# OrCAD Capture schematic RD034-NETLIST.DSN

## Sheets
1 6: size A3
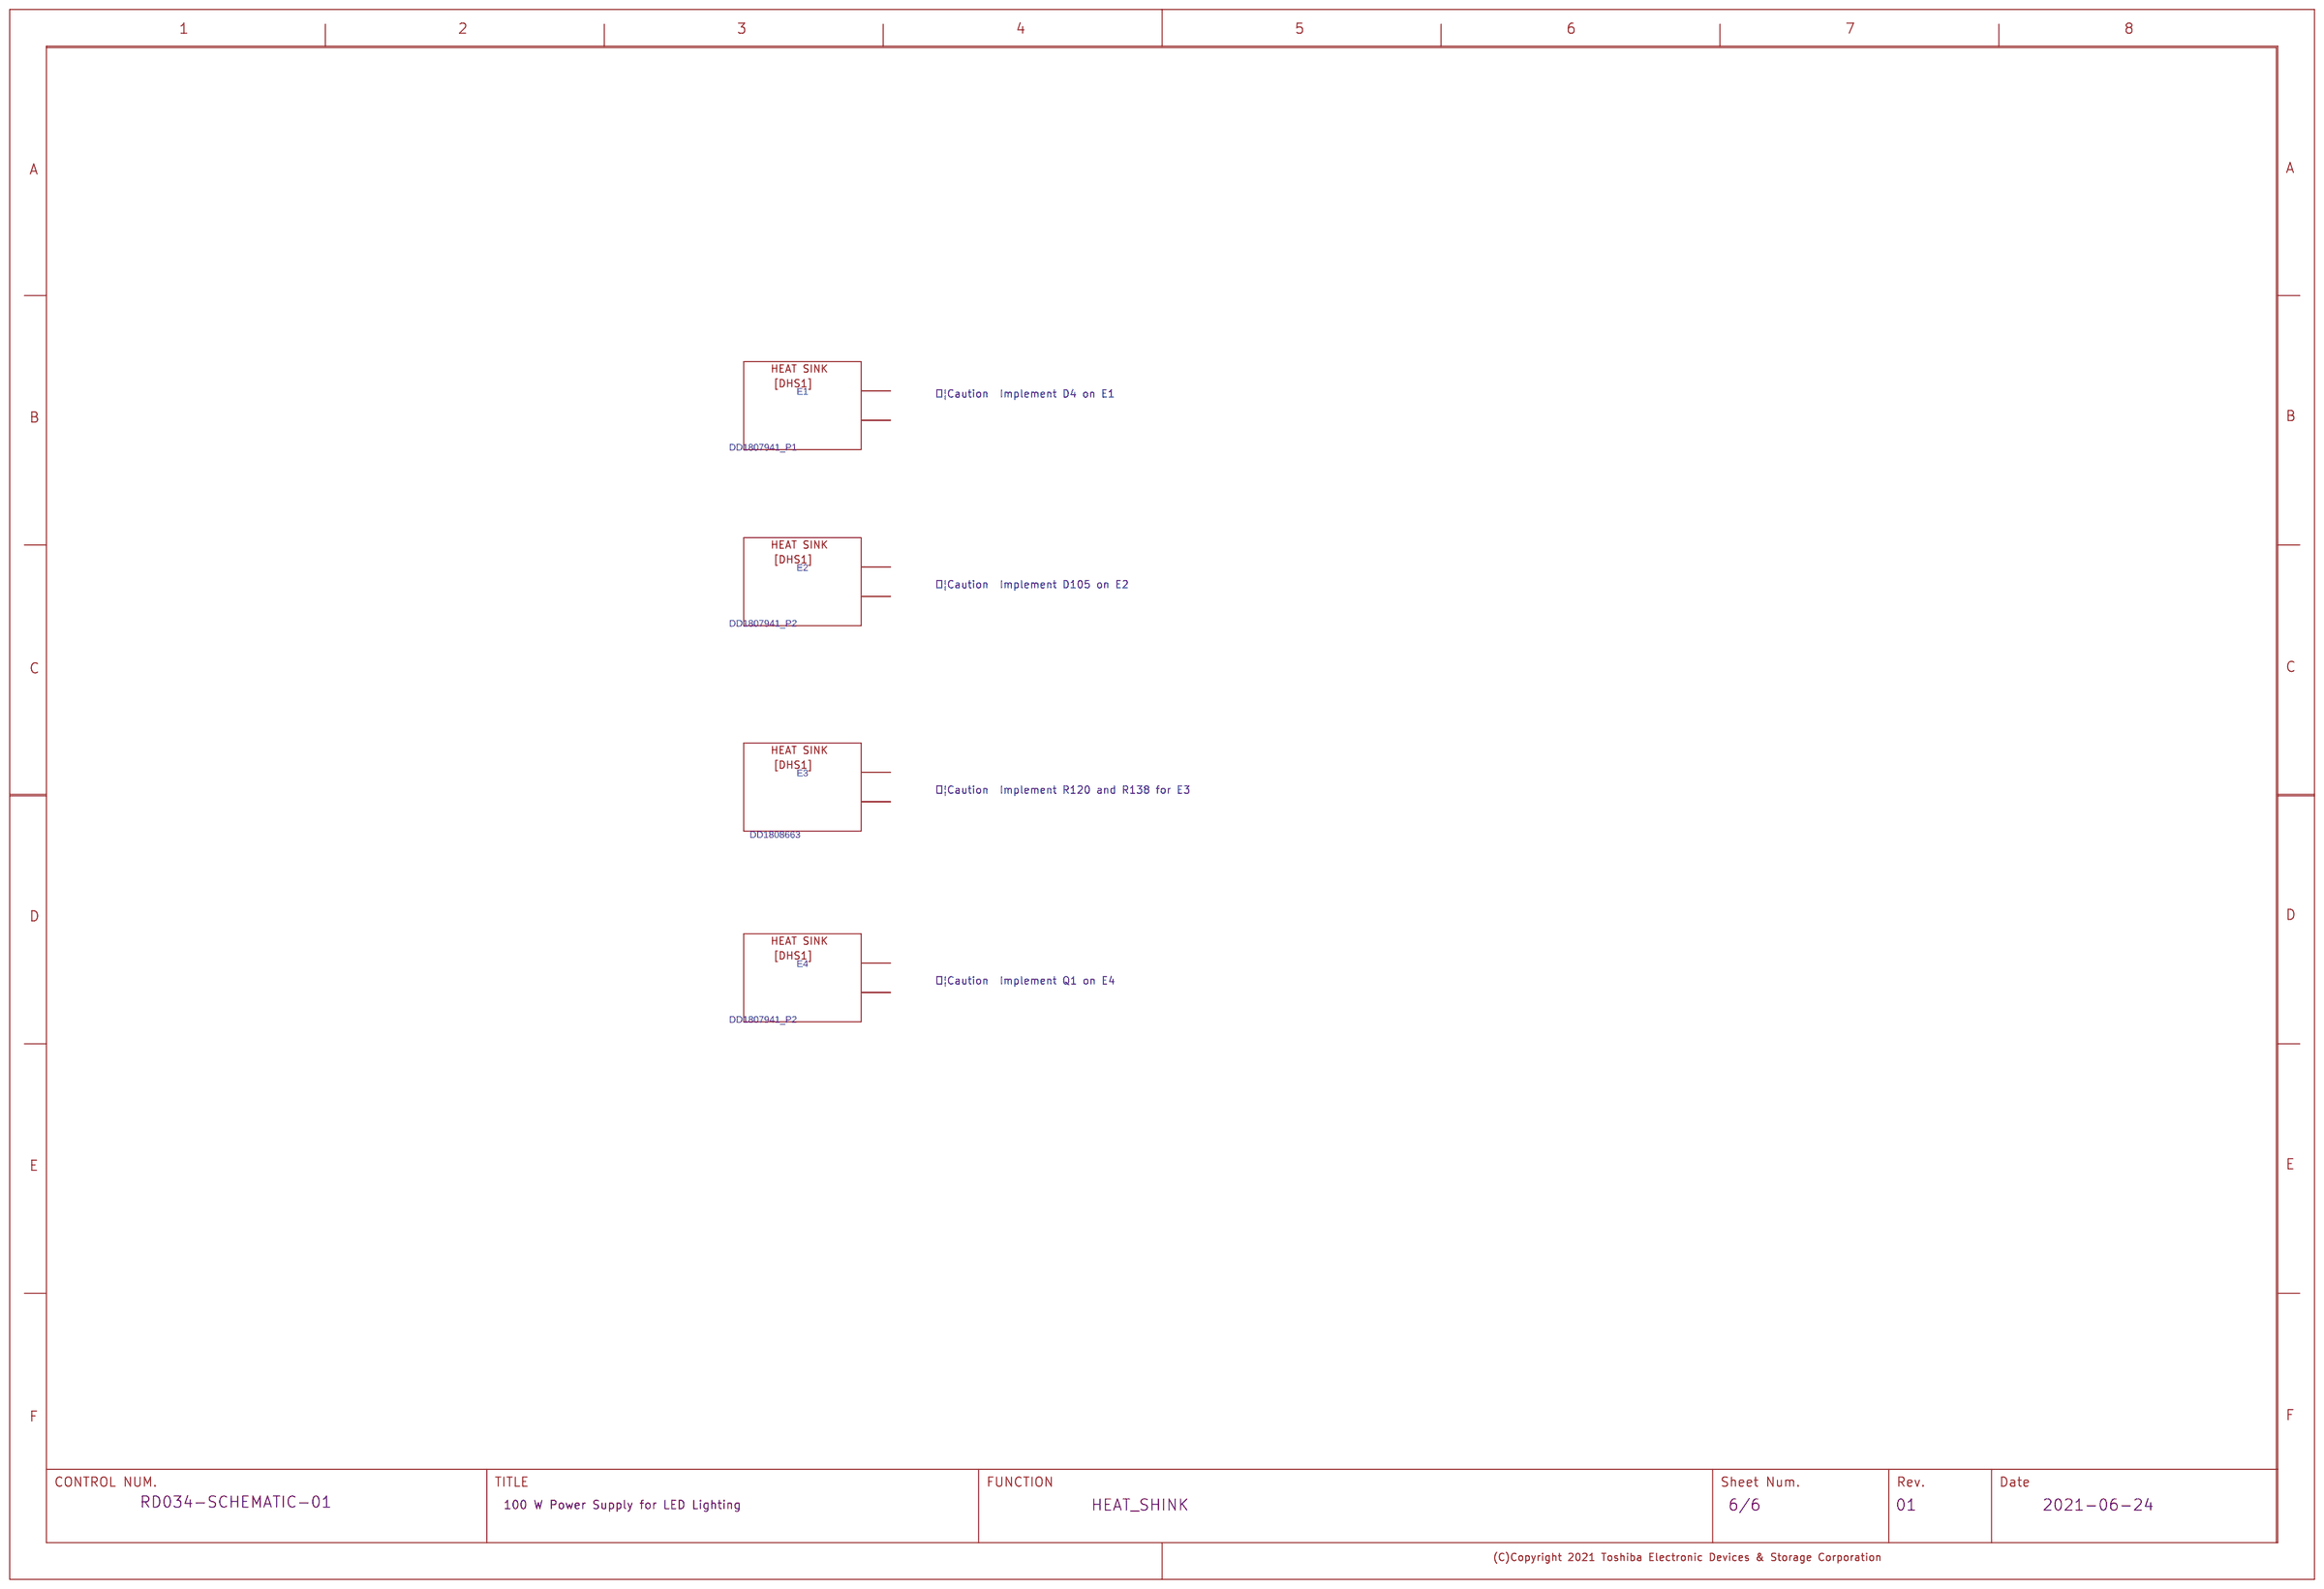
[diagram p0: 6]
2 5: size A3
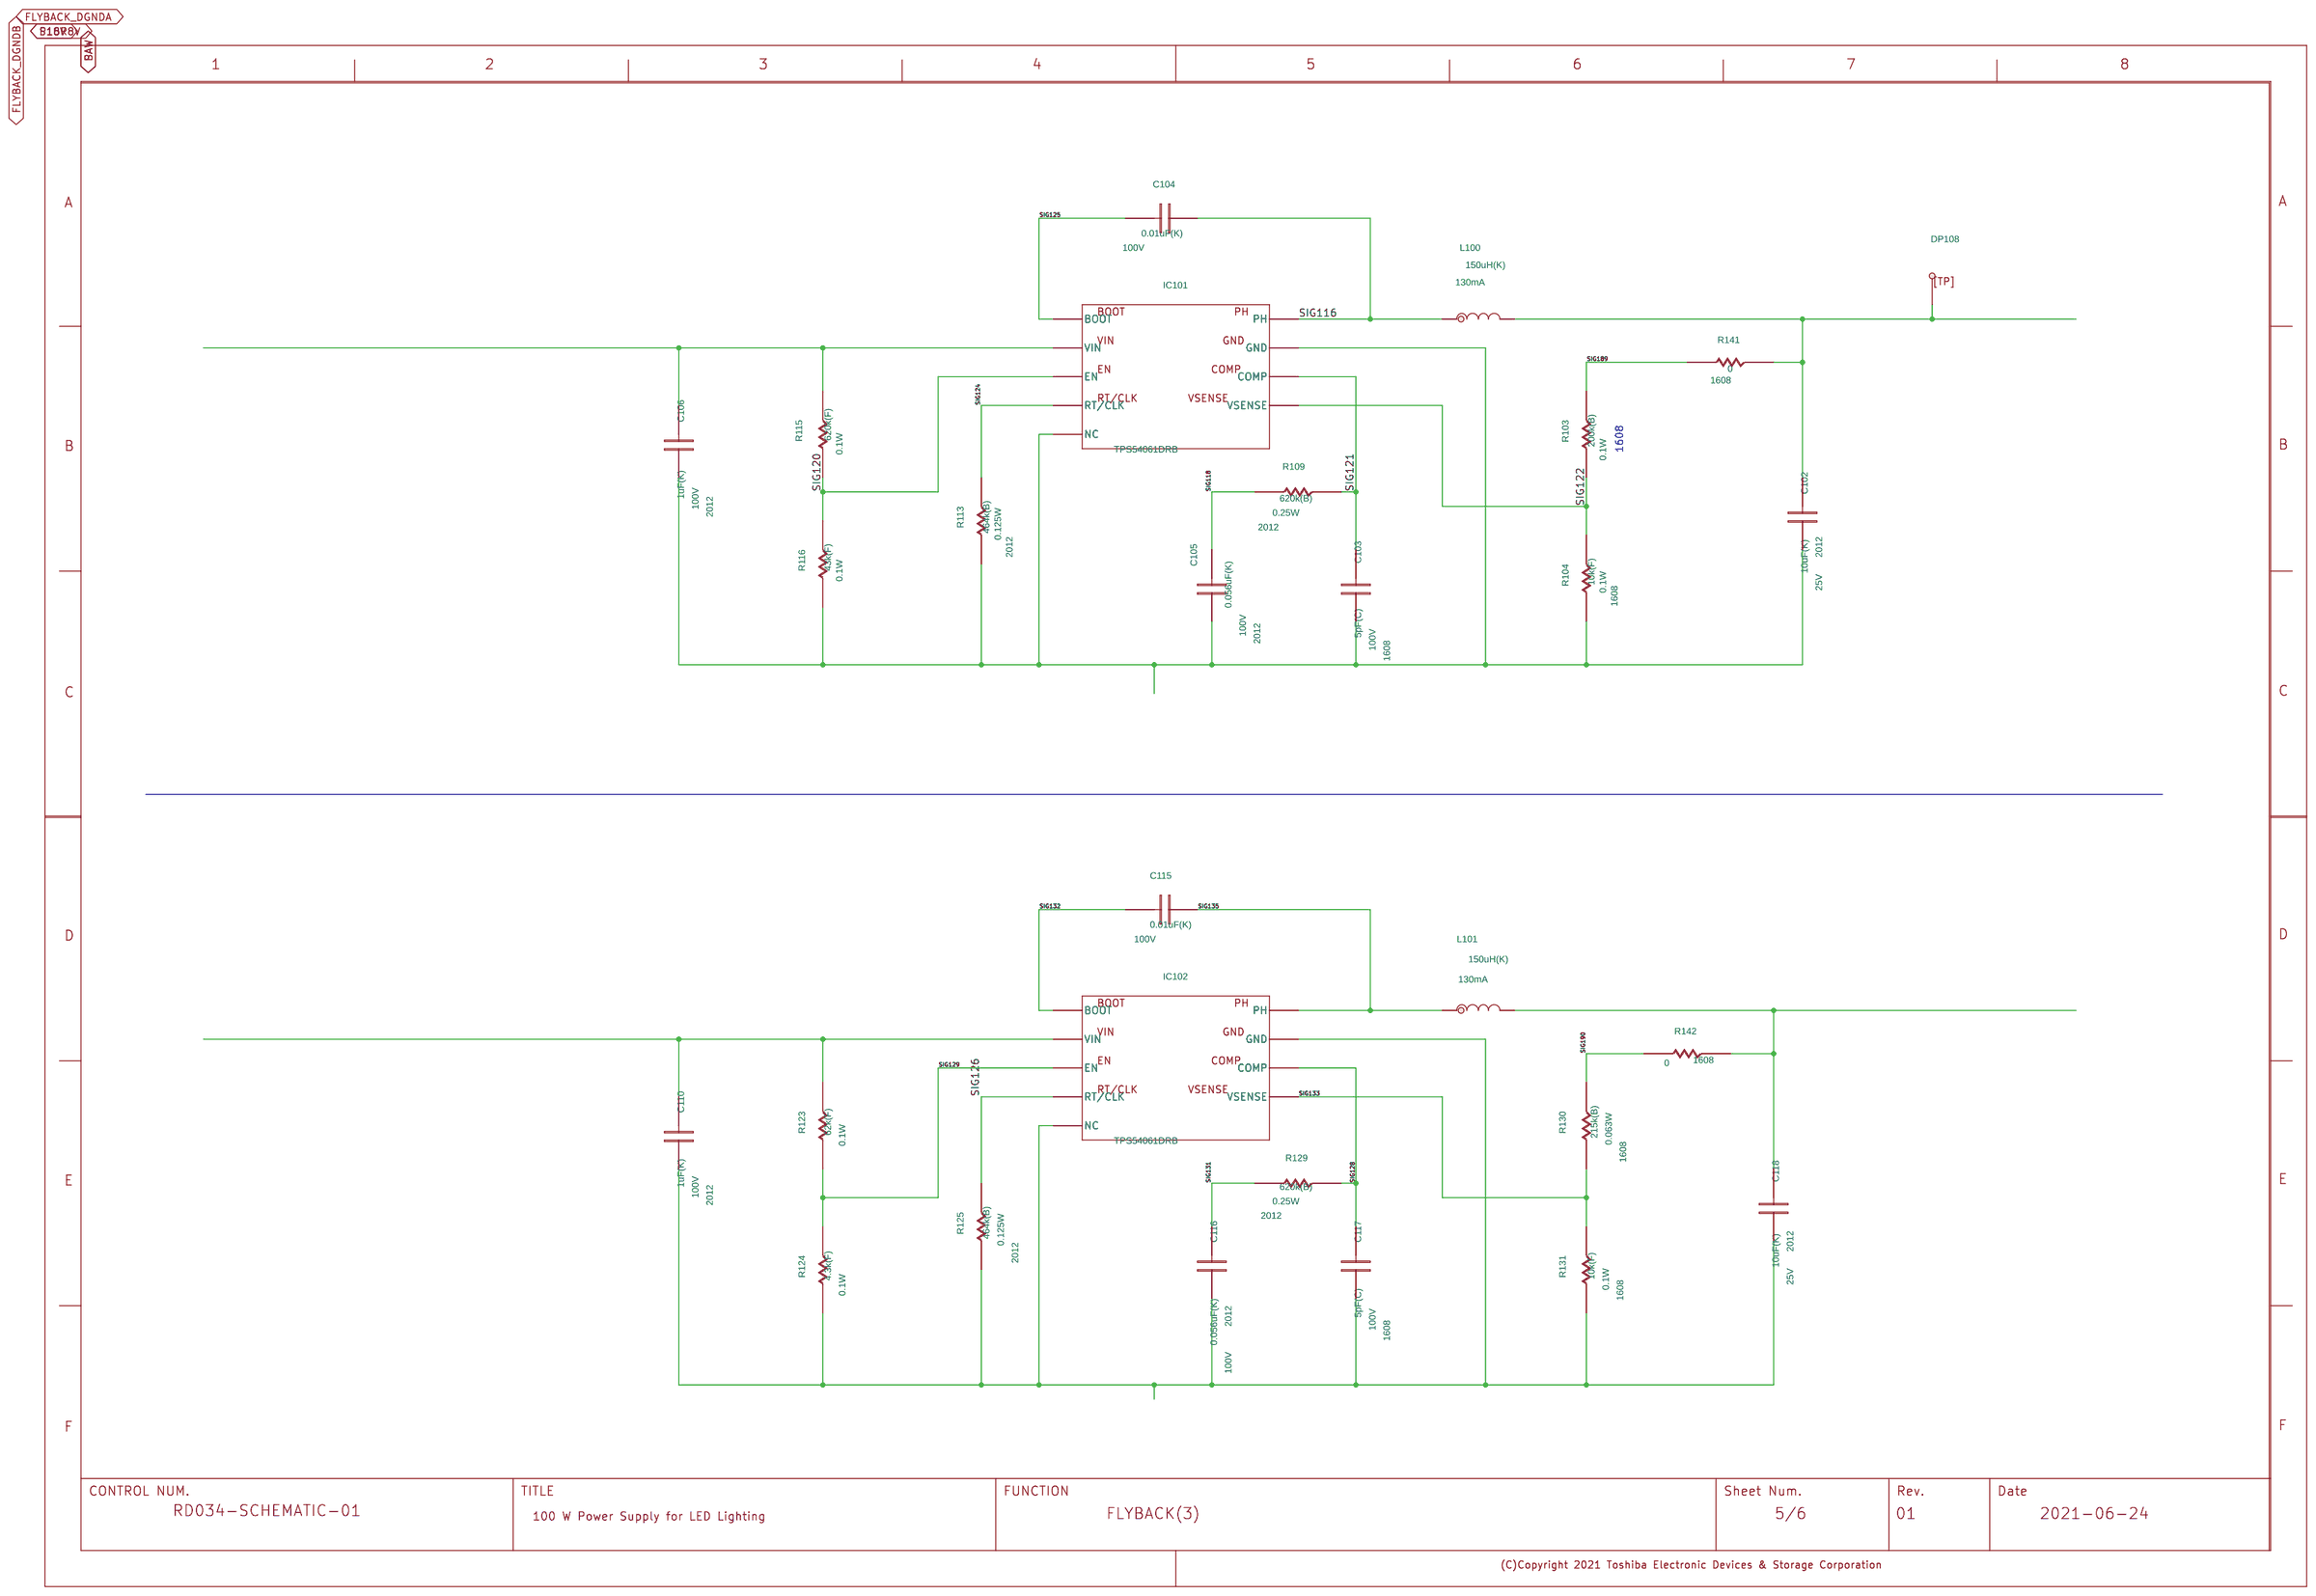
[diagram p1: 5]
3 4: size A3
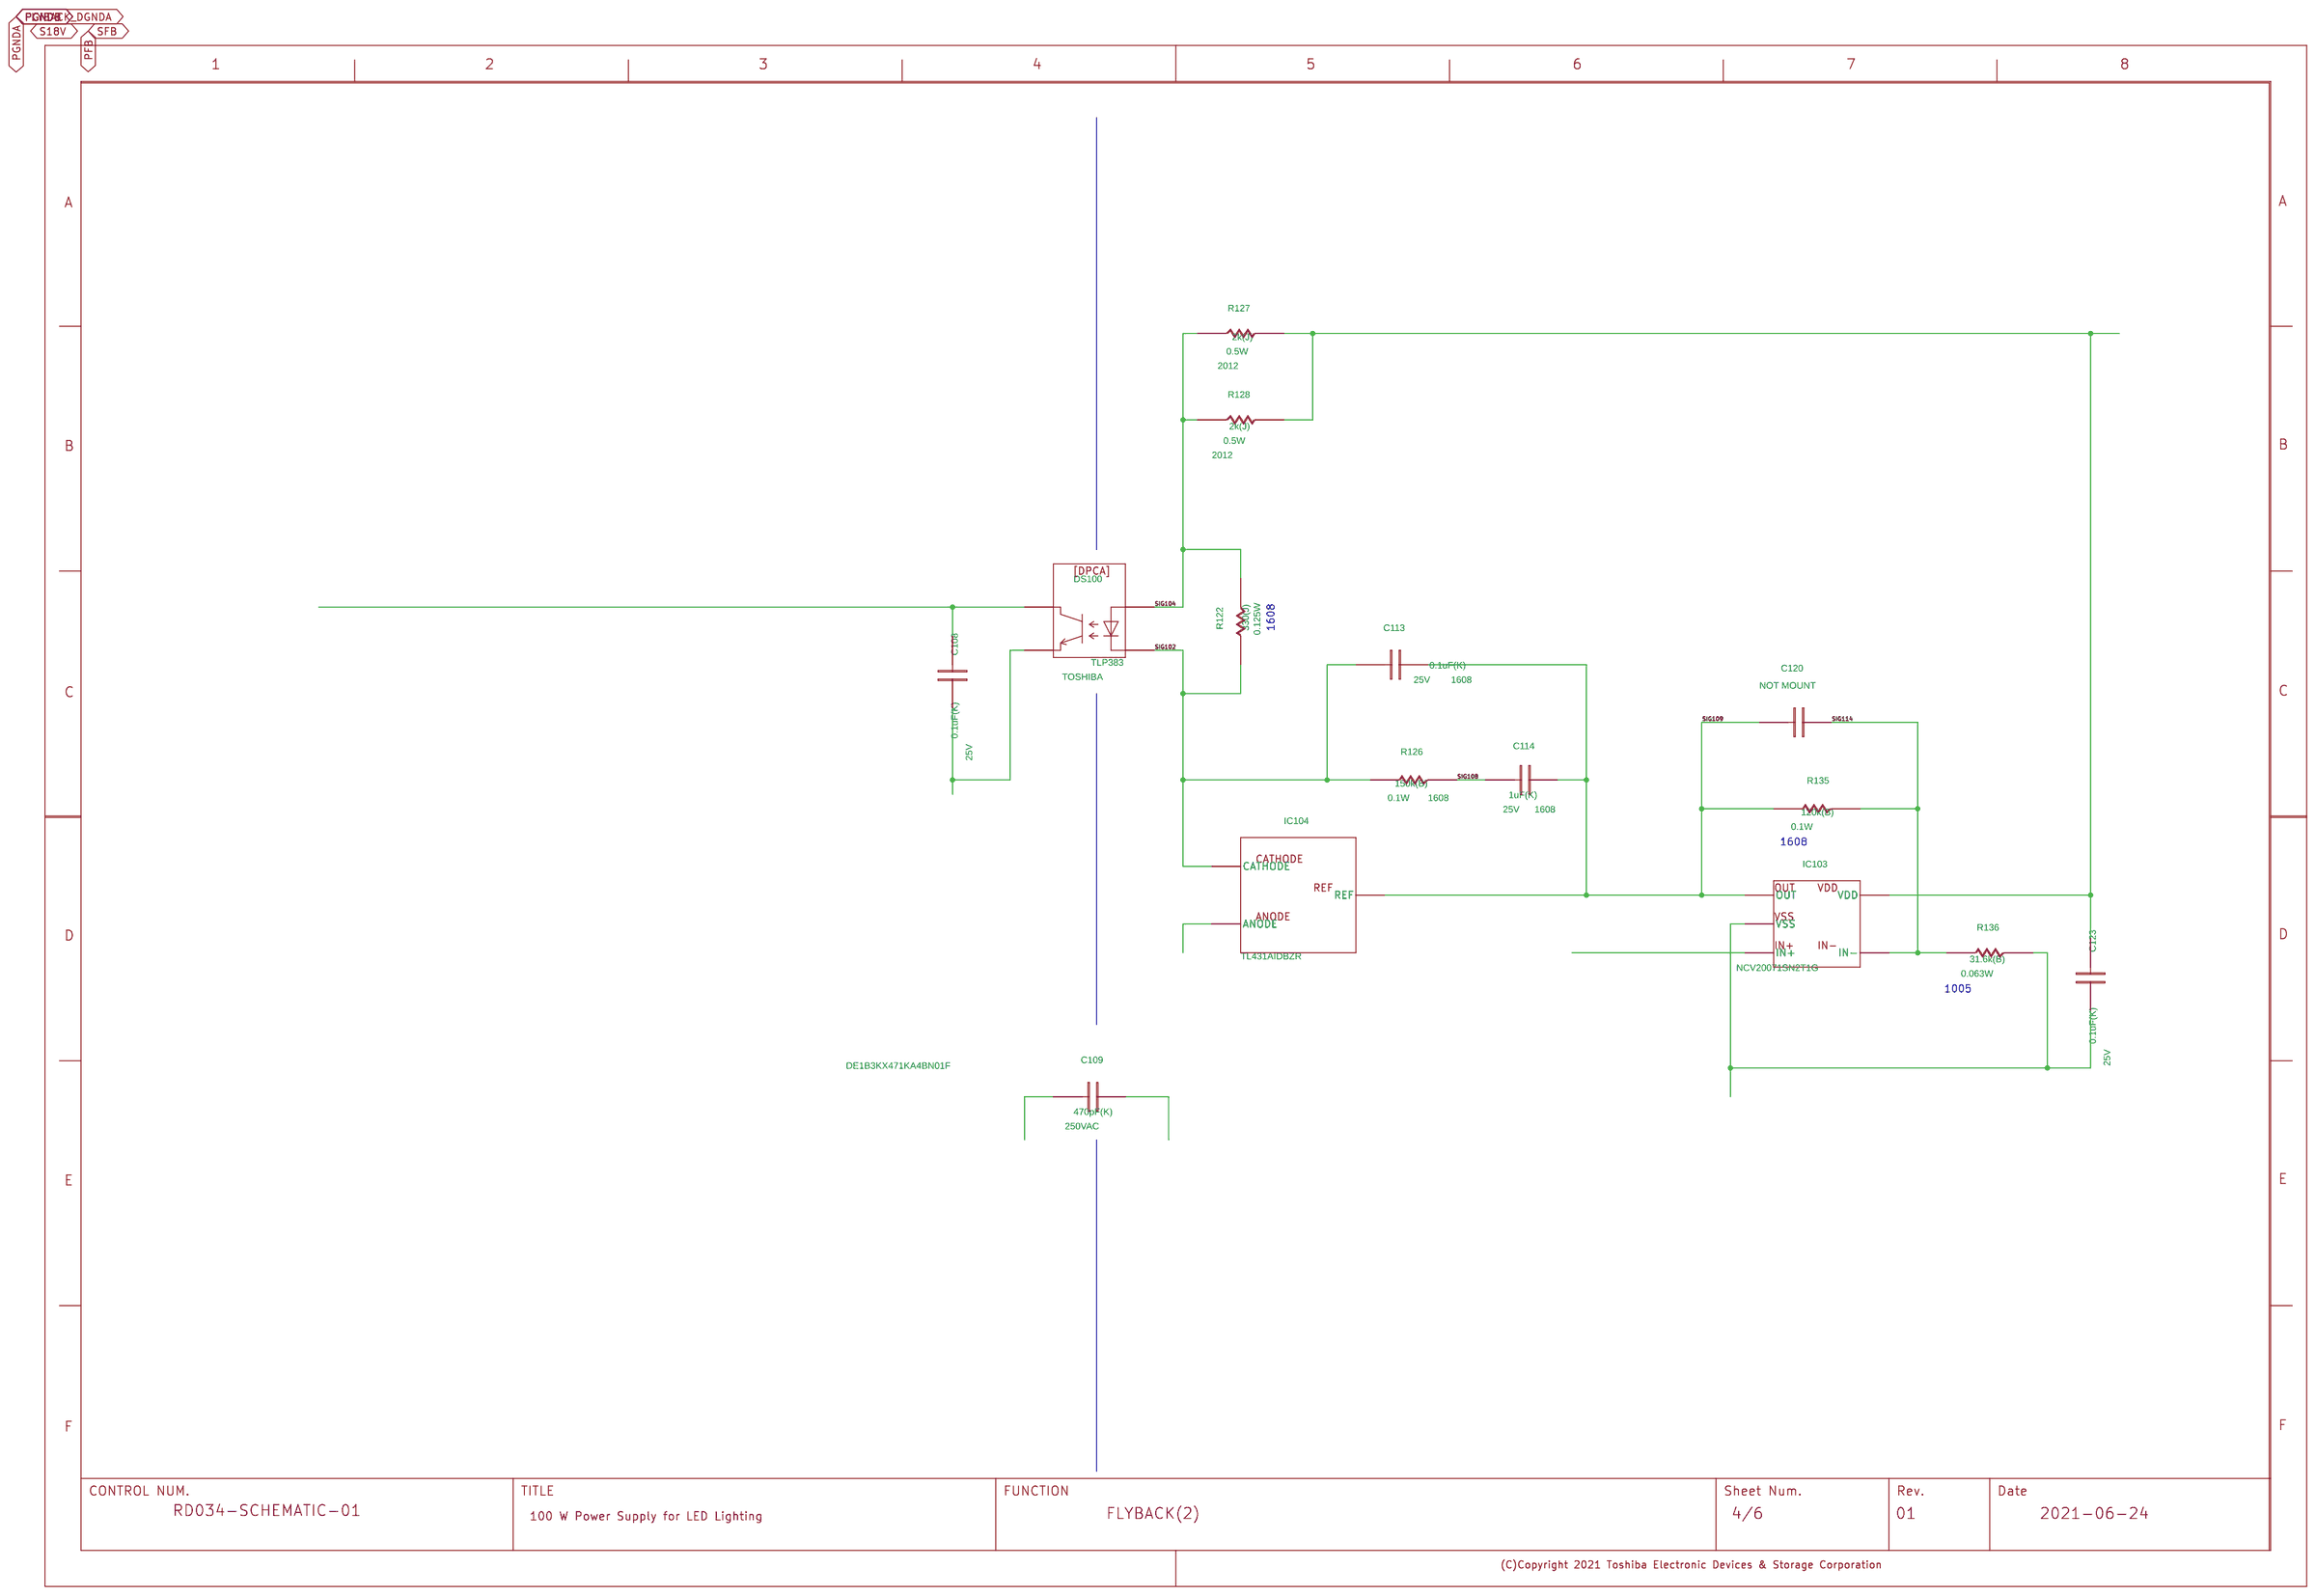
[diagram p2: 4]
4 3: size A3
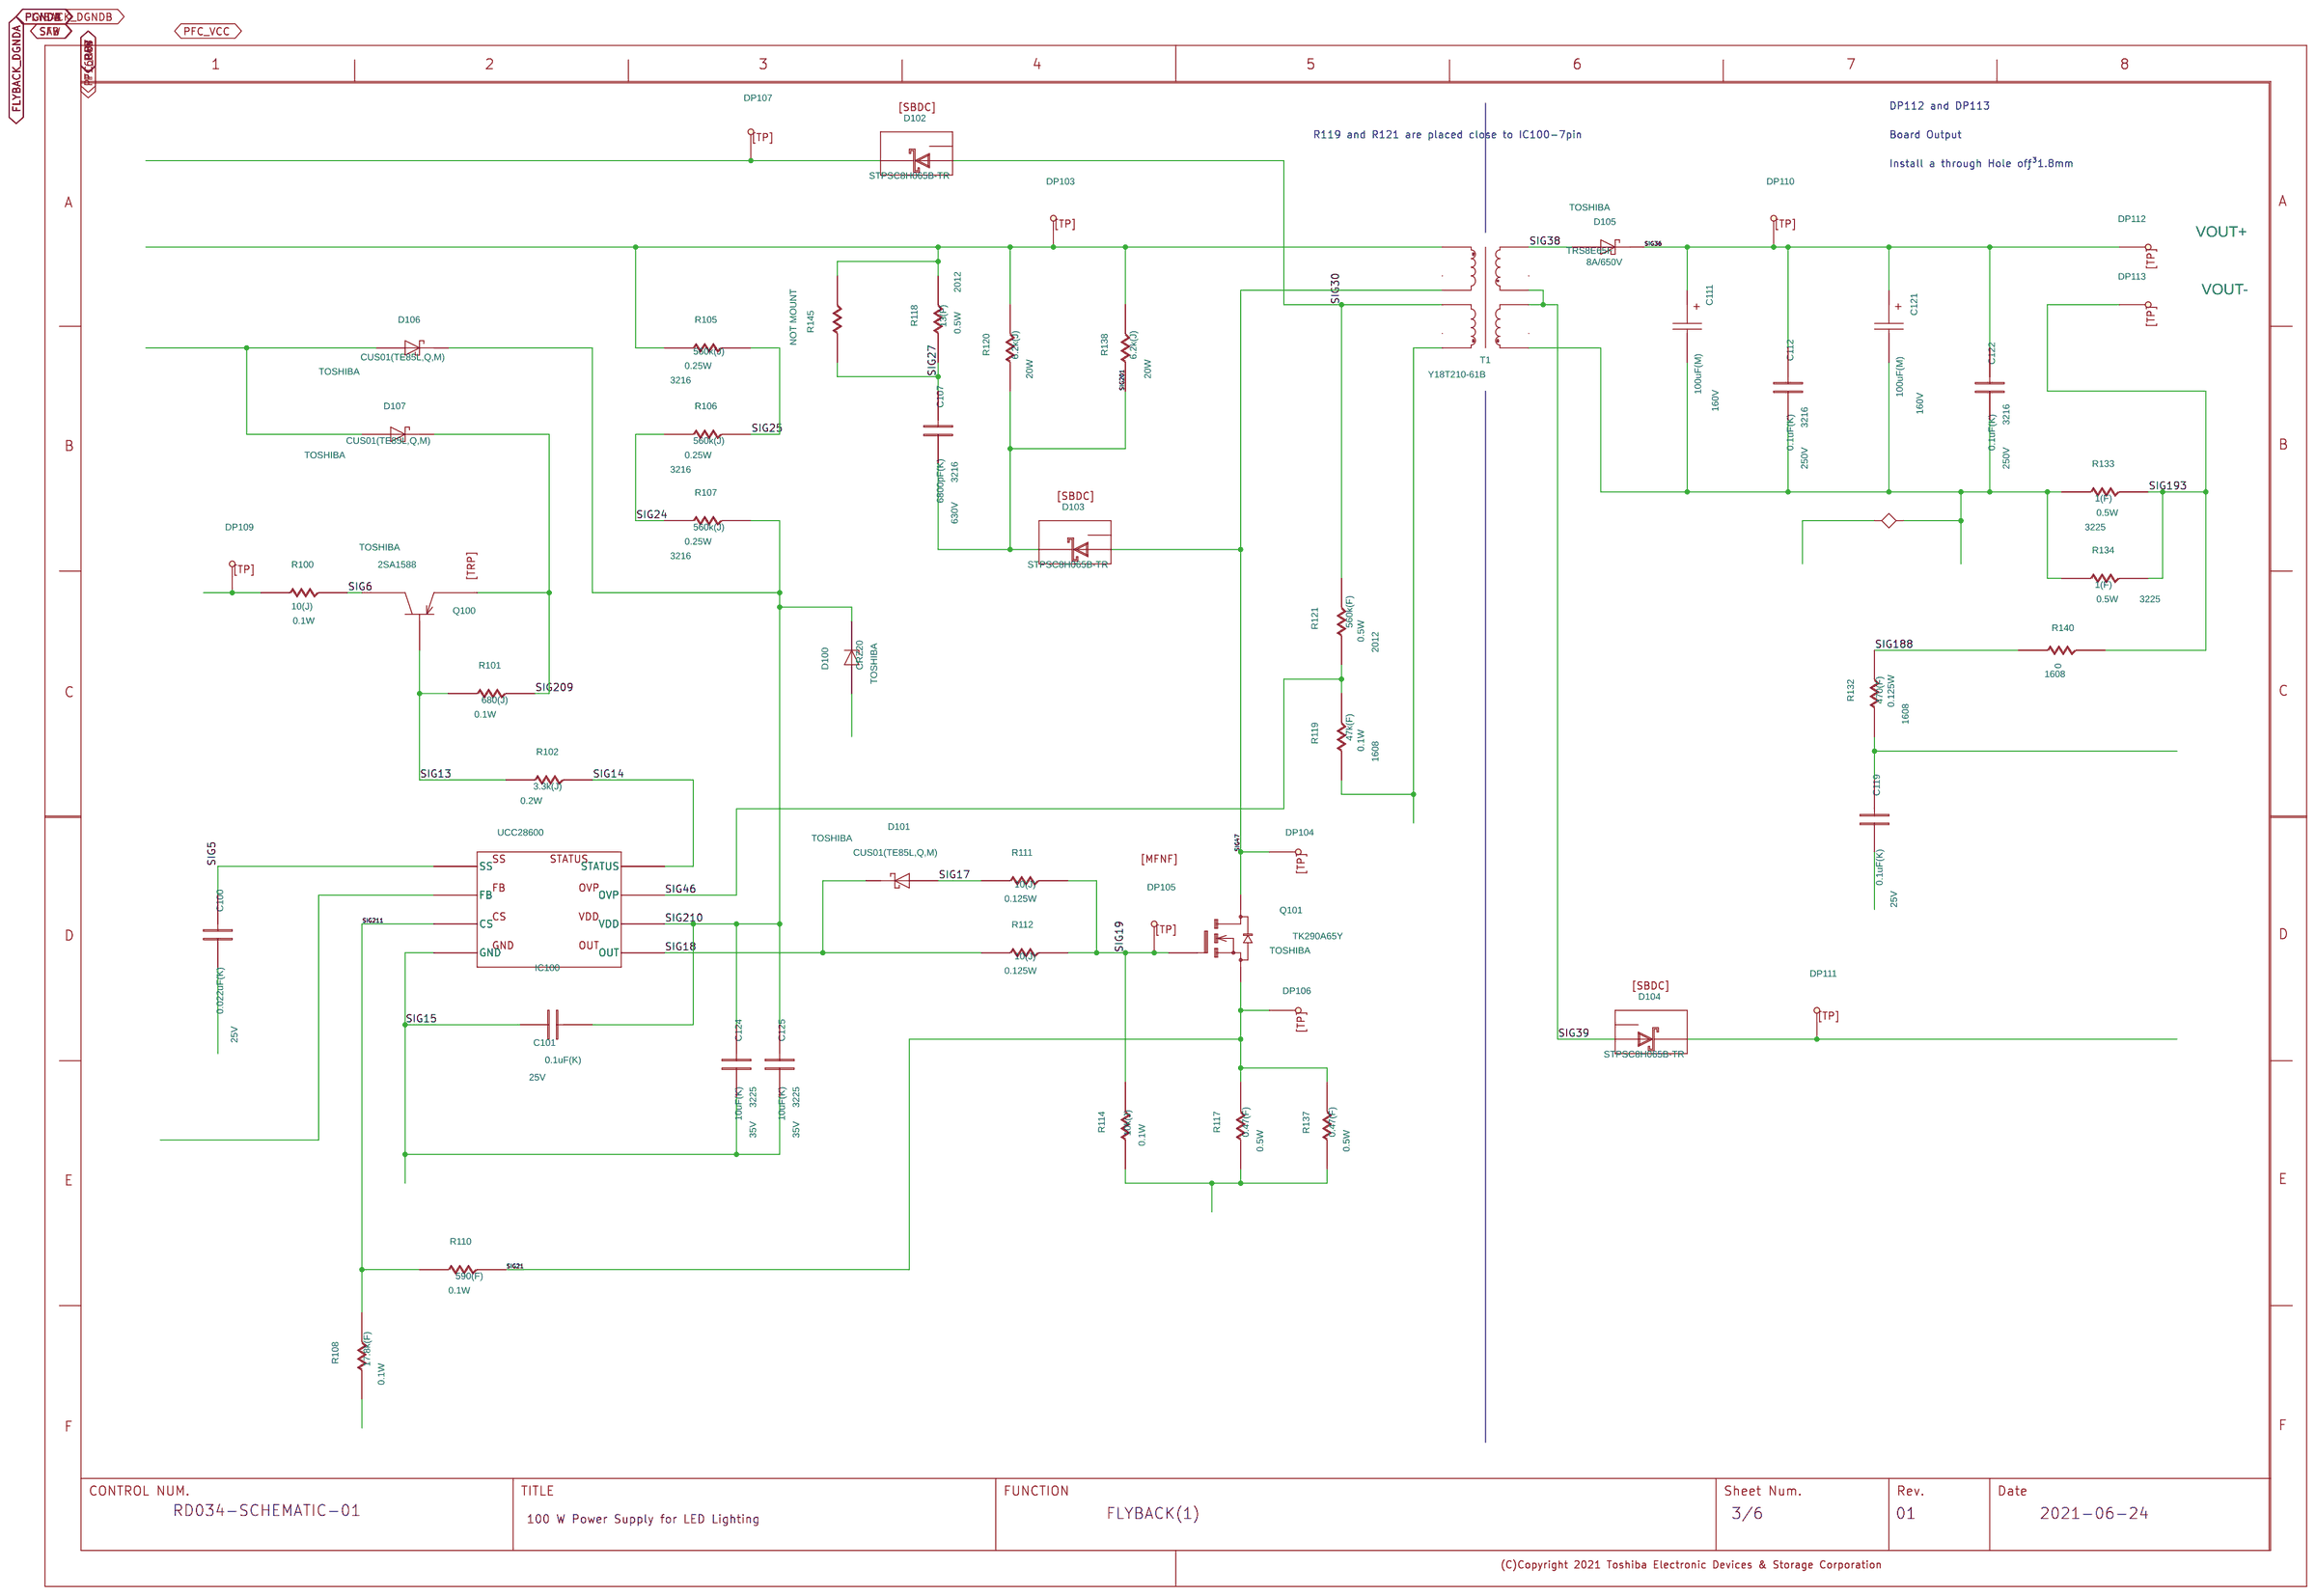
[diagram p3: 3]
5 2: size A3
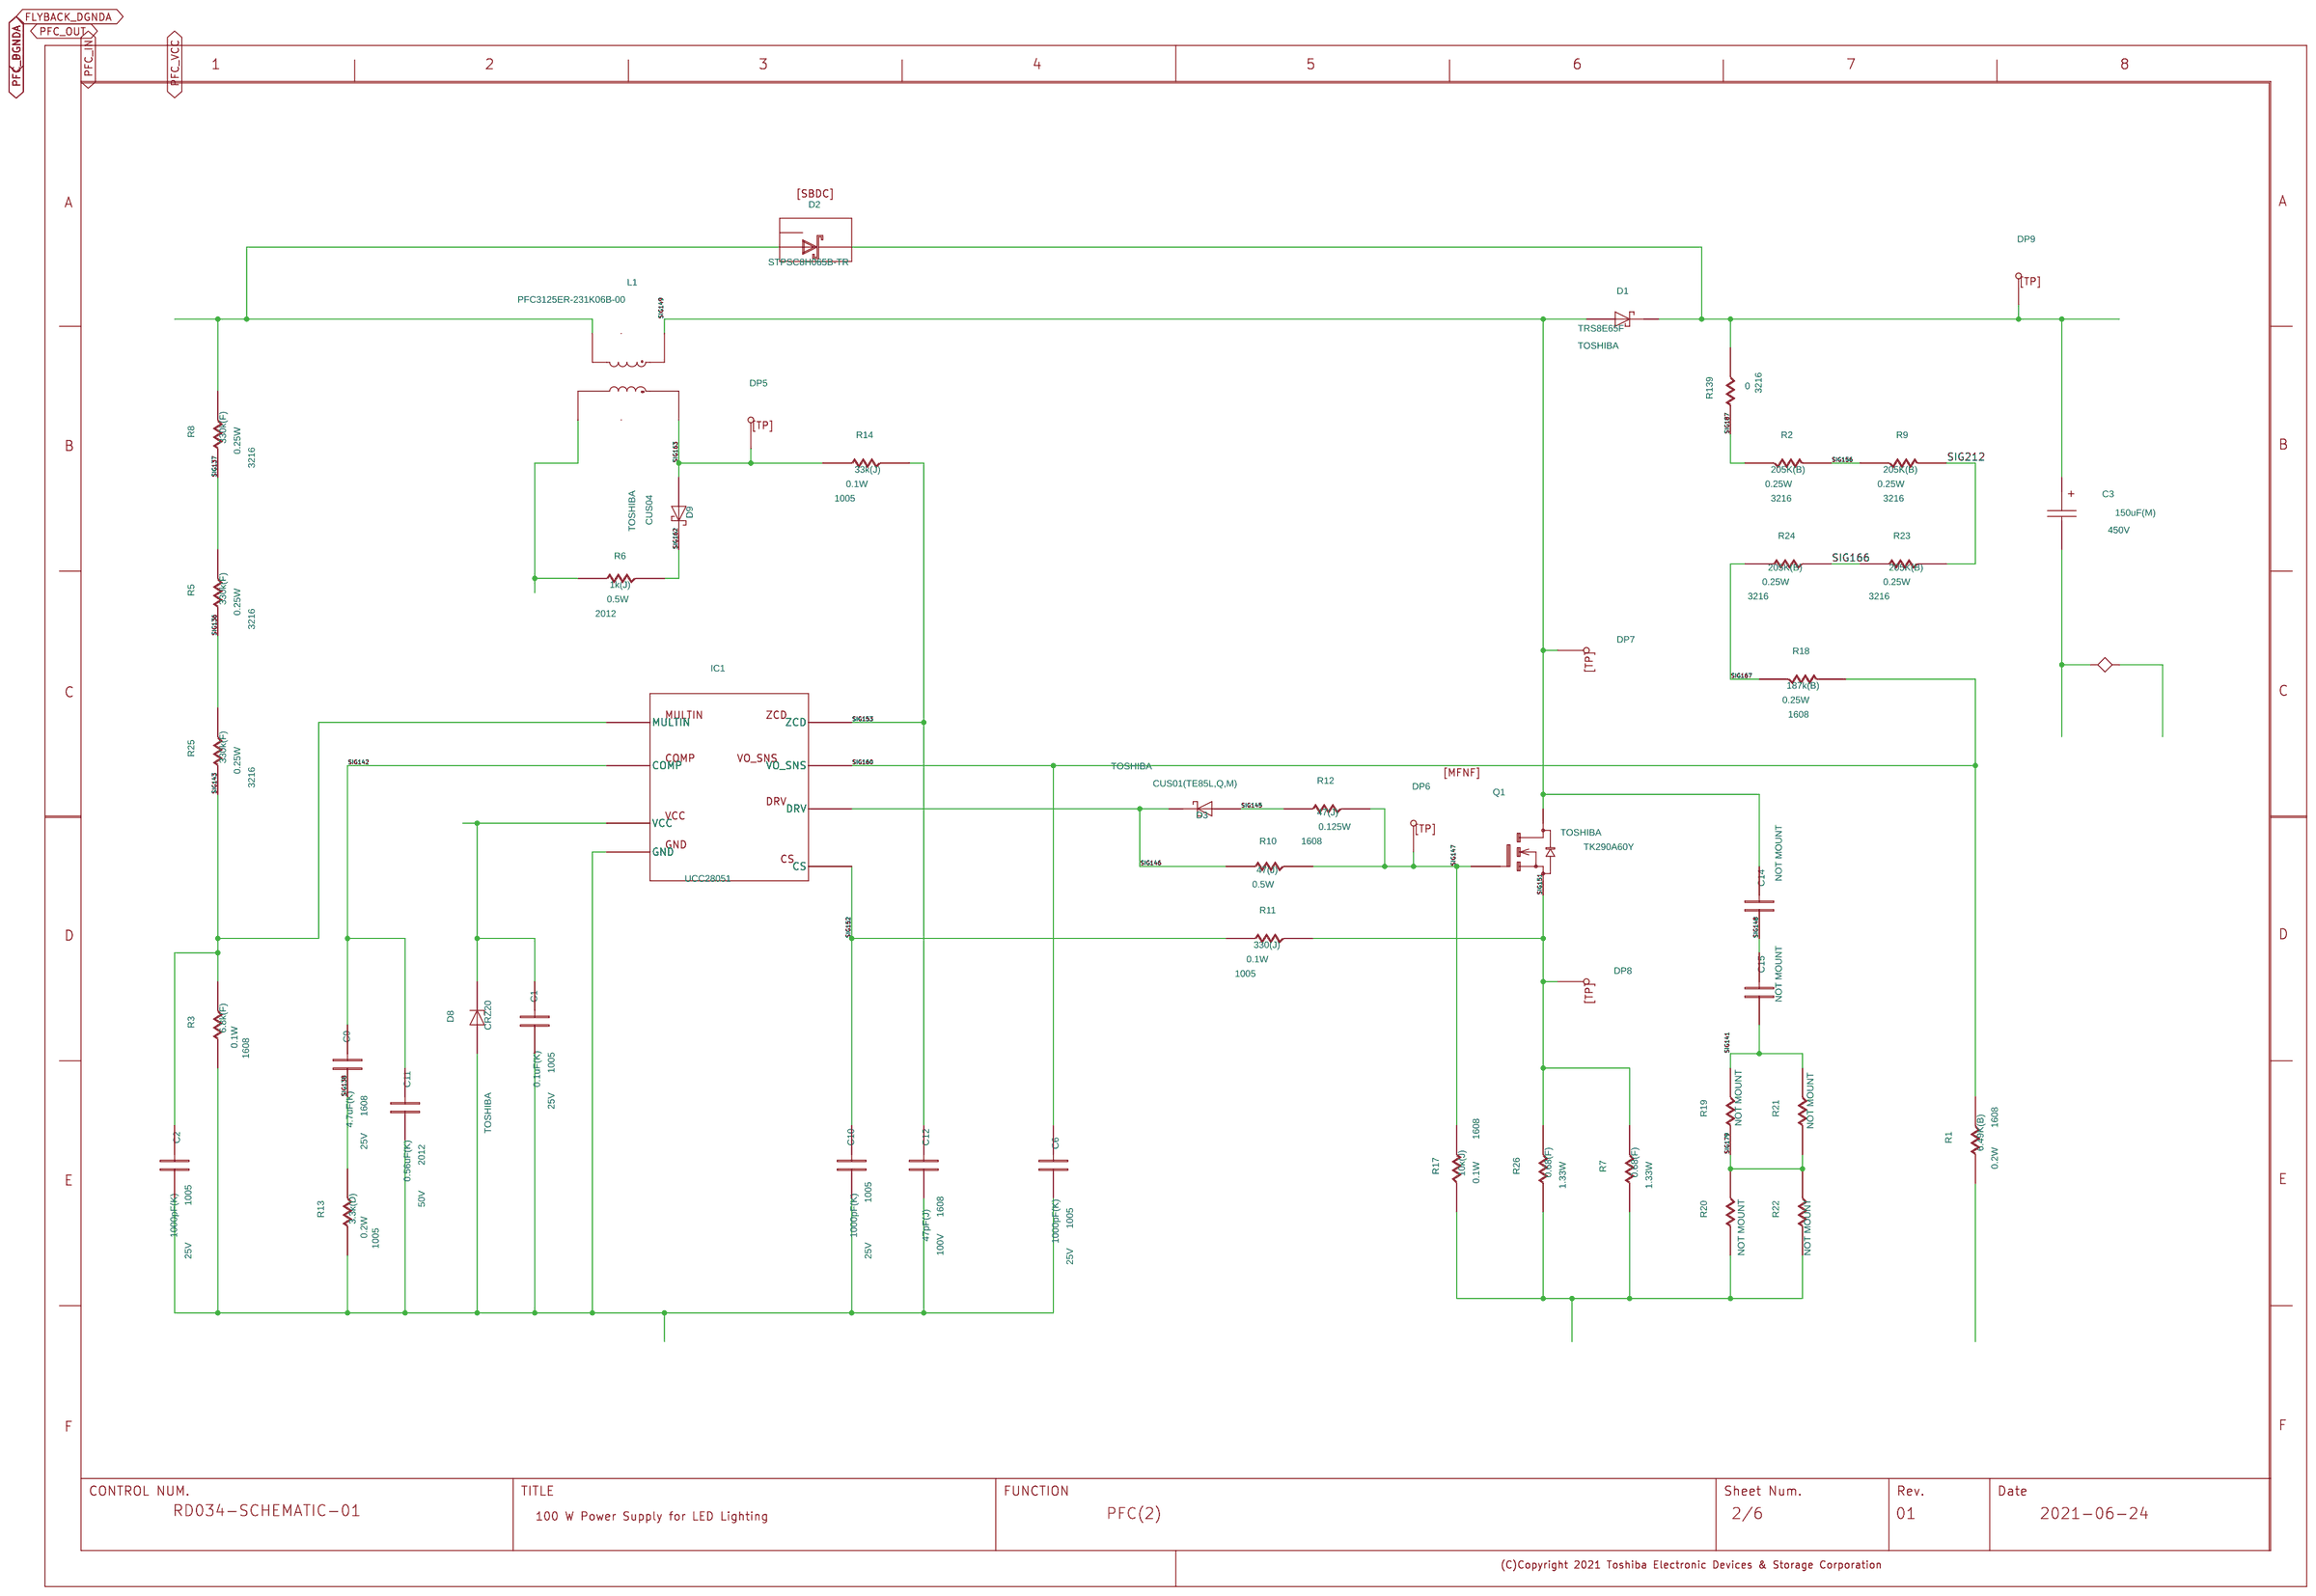
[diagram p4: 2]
6 1: size A3
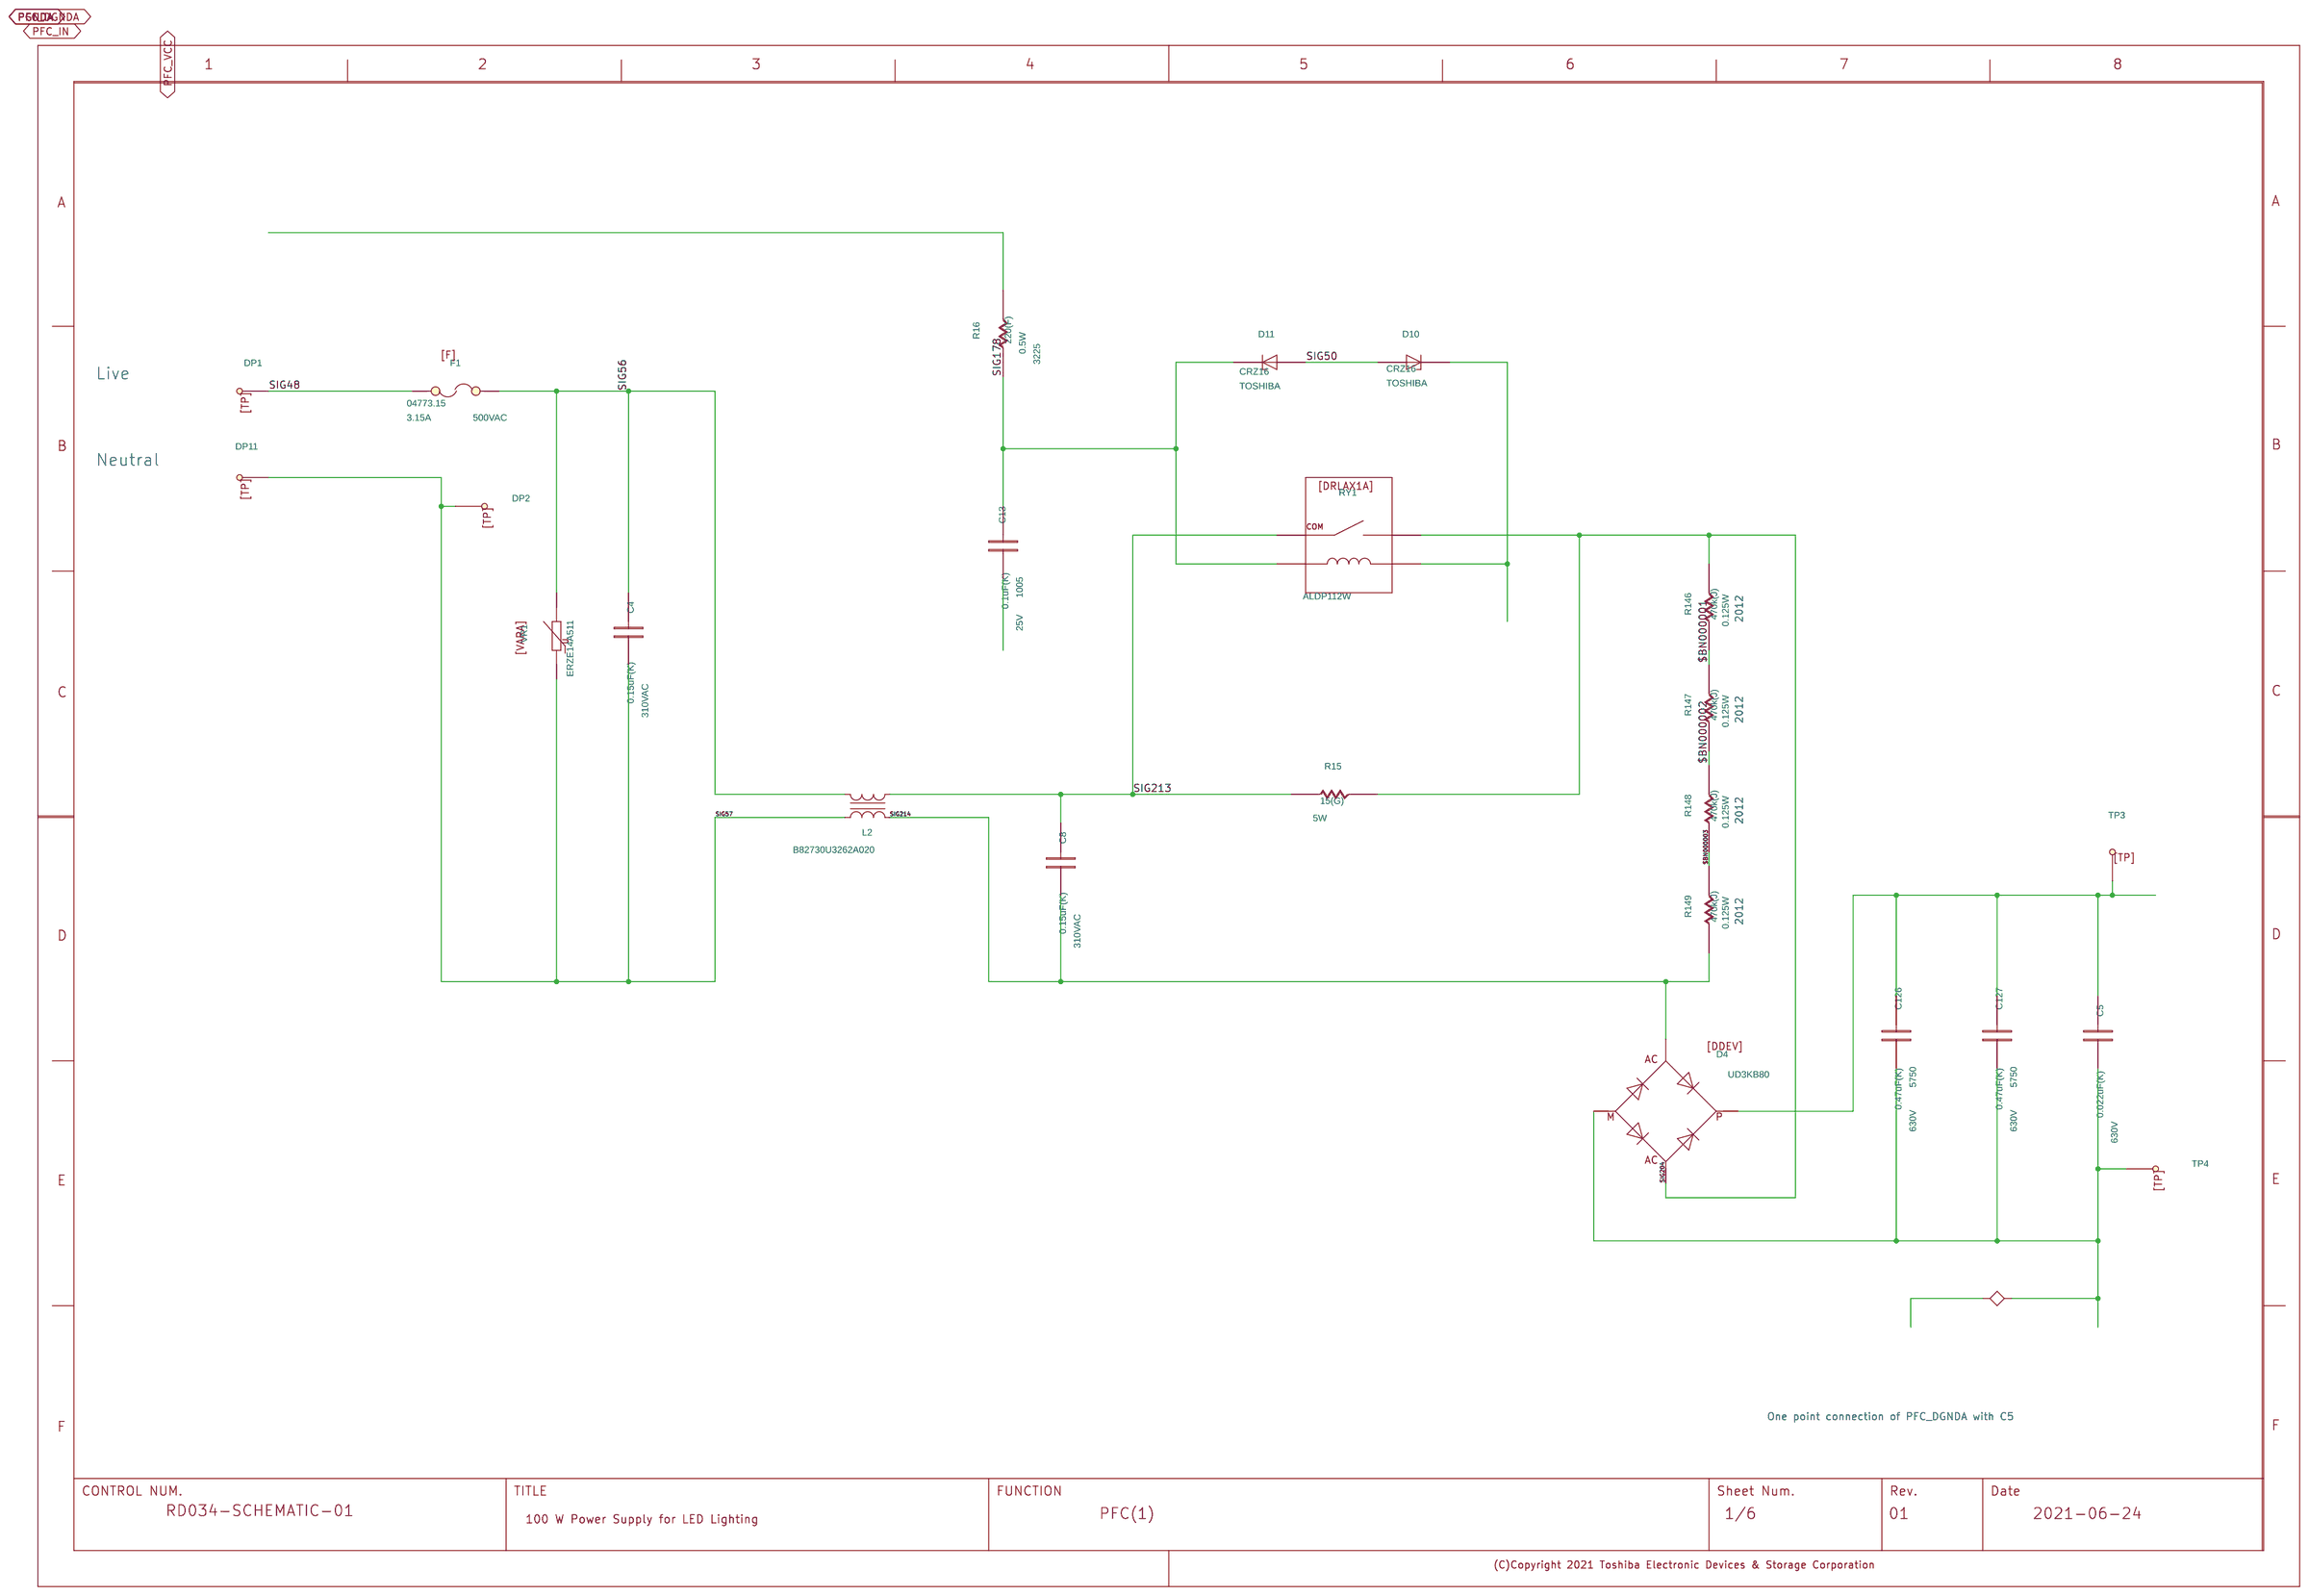
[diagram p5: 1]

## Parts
sheet 1
C4  DC
C5  DC
C8  DC
C13  DC
C126  DC
C127  DC
D4  DDEV
D10  DZD2
D11  DZD2
DP1  DTP
DP2  DTP
DP11  DTP
F1  DF
L2  CMF_2P_CMF_2P
R15  DR
R16  DR
R146  DR
R147  DR
R148  DR
R149  DR
RY1  DRLAX1A
STAR2  STAR2
TP3  DTP
TP4  DTP
U?#5  WAKU_DEF100_2021
VR1  DVARA
sheet 2
C1  DC
C2  DC
C3  DCP2
C6  DC
C9  DC
C10  DC
C11  DC
C12  DC
C14  DC
C15  DC
D1  DSBD2
D2  DSBDC2
D3  DSBD2
D8  DZD2
D9  DSBD2
DP5  DTP
DP6  DTP
DP7  DTP
DP8  DTP
DP9  DTP
IC1  UCC28051
L1  PFC3125ER-231K06B-00
Q1  DMFNF
R1  DR
R2  DR
R3  DR
R5  DR
R6  DR
R7  DR
R8  DR
R9  DR
R10  DR
R11  DR
R12  DR
R13  DR
R14  DR
R17  DR
R18  DR
R19  DR
R20  DR
R21  DR
R22  DR
R23  DR
R24  DR
R25  DR
R26  DR
R139  DR
STAR1  STAR2
U?#4  WAKU_DEF100_2021
sheet 3
C100  DC
C101  DC
C107  DC
C111  DCP2
C112  DC
C119  DC
C121  DCP2
C122  DC
C124  DC
C125  DC
D100  DZD2
D101  DSBD2
D102  DSBDC2
D103  DSBDC2
D104  DSBDC2
D105  DSBD2
D106  DSBD2
D107  DSBD2
DP103  DTP
DP104  DTP
DP105  DTP
DP106  DTP
DP107  DTP
DP109  DTP
DP110  DTP
DP111  DTP
DP112  DTP
DP113  DTP
IC100  UCC28600
Q100  DTRP
Q101  DMFNF
R100  DR
R101  DR
R102  DR
R105  DR
R106  DR
R107  DR
R108  DR
R110  DR
R111  DR
R112  DR
R114  DR
R117  DR
R118  DR
R119  DR
R120  DR
R121  DR
R132  DR
R133  DR
R134  DR
R137  DR
R138  DR
R140  DR
R145  DR
STAR3  STAR2
T1  TRANS1
U?#3  WAKU_DEF100_2021
sheet 4
C108  DC
C109  DC
C113  DC
C114  DC
C120  DC
C123  DC
DS100  TLP383
IC103  NCV20071SN2T1G
IC104  TL431AIDBZR
R122  DR
R126  DR
R127  DR
R128  DR
R135  DR
R136  DR
U?#2  WAKU_DEF100_2021
sheet 5
C102  DC
C103  DC
C104  DC
C105  DC
C106  DC
C110  DC
C115  DC
C116  DC
C117  DC
C118  DC
DP108  DTP
IC101  TPS54061DRB2
IC102  TPS54061DRB2
L100  DL1D
L101  DL1D
R103  DR
R104  DR
R109  DR
R113  DR
R115  DR
R116  DR
R123  DR
R124  DR
R125  DR
R129  DR
R130  DR
R131  DR
R141  DR
R142  DR
U?#1  WAKU_DEF100_2021
sheet 6
E1  DHS1
E2  DHS1
E3  DHS1
E4  DHS1
U?#6  WAKU_DEF100_2021

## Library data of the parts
C4 C8 = DC: ADSCNVFLAG: ON; CAPACITANCETOLE: M; CDMASTERCADCELG: RD1001; COMPCOMMENT: 0.15Ê/10%/310u`b ;Wurth Electronics ;890334023025 ;- ;13~7~12o; COMPONENTTYPE: 4; FNLEADFREETHET1GT2GMCTH1: N_N_N; GCOUNT: 1; ICX_PART_MODEL: CON_330n; MAXGCOUNT: 1; NOMINALCAPACITA: 330n; OUMECLASSIFICATION: ƒtƒBƒ‹ƒƒRƒ“ƒfƒ“ƒT; OUMEMAKERKATAMEI: B32922C3334M; OUMEPARTTYPE: C; PARTNAME: 890334023025; RATEDVOLTAGE: 305; VAL1: 0.15uF(K); VAL2: 310VAC; VAL3: 890334023025
C5 = DC: ADSCNVFLAG: ON; CAPACITANCETOLE: M; CDMASTERCADCELG: RD1001; COMPCOMMENT: 0.022Ê/10%/630V ;Panasonic ;ECQE6223KF ;- ;12.00mm x 5.30mm~11.50; COMPONENTTYPE: 4; FNLEADFREETHET1GT2GMCTH1: N_N_N; GCOUNT: 1; ICX_PART_MODEL: CON_330n; MAXGCOUNT: 1; NOMINALCAPACITA: 330n; OUMECLASSIFICATION: ƒtƒBƒ‹ƒƒRƒ“ƒfƒ“ƒT; OUMEMAKERKATAMEI: B32922C3334M; OUMEPARTTYPE: C; PARTNAME: ECQE6223KF; RATEDVOLTAGE: 305; VAL1: 0.022uF(K); VAL2: 630V; VAL3: ECQE6223KF
C1 C13 C101 C108 C119 C123 = DC: ADSCNVFLAG: ON; ADSCOMPONENTNAME: C_1005; ADSMODELNAME: s_GRM155R61E104KA87D; CAPACITANCETOLE: K; CDMASTERCADCELG: KC0005; COMPCOMMENT: 0.1u/10%/25V ;MURATA ;GRM155R61E104KA87D ;1005 ;-; COMPONENTTYPE: 4; FNLEADFREETHET1GT2GMCTH1: N_N_N; GCOUNT: 1; ICX_PART_MODEL: CON_100n; MAXGCOUNT: 1; NOMINALCAPACITA: 100n; OUMECLASSIFICATION: ƒZƒ‰ƒ~ƒbƒNƒRƒ“ƒfƒ“ƒT; OUMEMAKER: MRT ºc»ì; OUMEMAKERKATAMEI: GRM155R61E104KA87D; OUMEPARTTYPE: C; PARTNAME: GRM155R61E104KA87D; RATEDVOLTAGE: 25; SIZECODESMD: 1005; VAL1: 0.1uF(K); VAL2: 25V; VAL3: GRM155R61E104KA87D
C126 C127 = DC: ADSCNVFLAG: ON; CAPACITANCETOLE: M; CDMASTERCADCELG: RD1001; COMPCOMMENT: 5750; COMPONENTTYPE: 4; FNLEADFREETHET1GT2GMCTH1: N_N_N; GCOUNT: 1; ICX_PART_MODEL: CON_330n; MAXGCOUNT: 1; NOMINALCAPACITA: 330n; OUMECLASSIFICATION: ƒtƒBƒ‹ƒƒRƒ“ƒfƒ“ƒT; OUMEMAKERKATAMEI: B32922C3334M; OUMEPARTTYPE: C; PARTNAME: C5750X7T2J474K250KC; RATEDVOLTAGE: 305; VAL1: 0.47uF(K); VAL2: 630V; VAL3: C5750X7T2J474K250KC
D4 = DDEV: ADSCNVFLAG: ON; ADSCOMPONENTNAME: D_DDEV; ADSMODELNAME: s_D25XB60; CDMASTERCADCELG: D0001A; COMPCOMMENT: UD3KB80 ;Shindengen ;UD3KB80 ;- ;-; COMPONENTTYPE: 4; FNLEADFREETHET1GT2GMCTH1: N_N_N; GCOUNT: 1; MAXGCOUNT: 1; MOUNTINGFORMSMD: DIP; OUMECLASSIFICATION: ‚»‚Ì‘¼; OUMEMAKER: SDG Vd³HÆ; OUMEMAKERKATAMEI: D25XB60; OUMEPARTTYPE: D; PARTNAME: UD3KB80; VAL1: UD3KB80; VAL3: UD3KB80
D10 D11 = DZD2: COMPCOMMENT: 16V ;TOSHIBA ;CRZ16 ;- ;3.5o~1.6o~0.98o; COMPONENTTYPE: 4; PARTNAME: CRZ16; USERCOMPTEXT3: TOSHIBA; VAL1: 16V; VAL3: CRZ16
DP1 = DTP: COMPCOMMENT: ³1.8oÌX[z[Æ·é; COMPONENTTYPE: 4; FUNCTION: Live; PARTNAME: TP-TH1.8-L3.5
DP2 DP7-DP9 DP103-DP106 = DTP: COMPONENTTYPE: 4; PARTNAME: TP-PAD-C2.0
DP11 = DTP: COMPCOMMENT: ³1.8oÌX[z[Æ·é; COMPONENTTYPE: 4; FUNCTION: Neutral; PARTNAME: TP-TH1.8-L3.5
F1 = DF: ADSCNVFLAG: ON; CDMASTERCADCELG: KCK0317; COMPCOMMENT: 3.15‚`/500‚u‚`‚b ;‚k‚‰‚”‚”‚…‚Œ‚†‚•‚“‚… ;04773.15 ;- ;-; COMPONENTTYPE: 4; FNLEADFREETHET1GT2GMCTH1: N_N_N; GCOUNT: 1; MAXGCOUNT: 1; NOTMOUNT: MOUNT; OUMECLASSIFICATION: q[Y; OUMEMAKER: LTT eq[Y; OUMEMAKERKATAMEI: 0451012.MRL; OUMEPARTTYPE: F; PARTNAME: 4773.15MXEP-AEP; RATEDCURRENT: 12; VAL1: 3.15A; VAL2: 500VAC; VAL3: 04773.15
L2 = DFL09I: ADSCNVFLAG: ON; ADSCOMPONENTNAME: FL_DFL09I; ADSMODELNAME: s_ACM1513-551-2PL-TLHF@FN; CDMASTERCADCELG: KC1043; COMPCOMMENT: 330uH/2.6A ;EPCOS/TDK ;B82730U3262A020 ;- ;16.50mm x 11.00mm~16.50mm; COMPONENTTYPE: 4; FNLEADFREETHET1GT2GMCTH1: N_N_N; GCOUNT: 1; IMPEDANCE: 550; MAXGCOUNT: 1; MOUNTINGFORMSMD: SMD; OUMECLASSIFICATION: R[hRCidlhpj; OUMEMAKER: TDK ‚s‚c‚j; OUMEMAKERKATAMEI: ACM1513-551-2PL-TLHF@FN; OUMEPARTTYPE: FL; PARTNAME: B82730U3262A020; RATEDCURRENT: 10; VAL1: 330uH; VAL2: 2.6A; VAL3: B82730U3262A020
R15 = DR: ADSCNVFLAG: ON; ADSCOMPONENTNAME: R_null; ADSMODELNAME: s_BWR5CN150J; CDMASTERCADCELG: DR0056; COMPCOMMENT: 15/2%/5W ;8mm~25mm ;-; COMPONENTTYPE: 4; FNLEADFREETHET1GT2GMCTH1: N_N_N; GCOUNT: 1; ICX_PART_MODEL: RES_15; MAXGCOUNT: 1; MOUNTINGFORMSMD: DIP; NOMINALRESISTAN: 15; OUMECLASSIFICATION: ÅèïRí; OUMEMAKER: KOA R[A; OUMEMAKERKATAMEI: BWR5CN150J; OUMEPARTTYPE: R; PARTNAME: ROX5SG15R; POWERRATING: 5; RESISTANCETOLER: J; SIZECODESMD: RD; VAL1: 15(G); VAL2: 5W
R16 = DR: ADSCNVFLAG: ON; ADSCOMPONENTNAME: R_3225; ADSMODELNAME: s_ERJ14YJ330U; CDMASTERCADCELG: DR903A; COMPCOMMENT: 220/1%/0.5W ;KOA ;RK73H2ETTD2200F ;3225 ;-; COMPONENTTYPE: 4; FNLEADFREETHET1GT2GMCTH1: N_N_N; GCOUNT: 1; ICX_PART_MODEL: RES_33; MAXGCOUNT: 1; MOUNTINGFORMSMD: SMD; NOMINALRESISTAN: 33; OUMECLASSIFICATION: ÅèïRí; OUMEMAKER: NAE pi\jbNGNgjbNfoCX; OUMEMAKERKATAMEI: ERJ14YJ330U; OUMEPARTTYPE: R; PARTNAME: RK73H2ETTD2200F; POWERRATING: 500m; RESISTANCETOLER: J; SIZECODESMD: 3225; VAL1: 220(F); VAL2: 0.5W; VAL3: RK73H2ETTD2200F
R146-R149 = DR: COMPCOMMENT: 470k/5%/0.125W ;PANASONIC ;ERJ6GEYJ474V ;2012 ;-; COMPONENTTYPE: 4; PARTNAME: ERJ6GEYJ474V; VAL1: 470k(J); VAL2: 0.125W; VAL3: ERJ6GEYJ474V
RY1 = DRLAX1A: ADSCNVFLAG: ON; CDMASTERCADCELG: OD1051; COMPCOMMENT: 5A/277VAC ;PANASONIC ;ALDP112W ;- ;20.5o~7.2o~15.3o,szw¦; COMPONENTTYPE: 4; FNLEADFREETHET1GT2GMCTH1: N_N_N; GCOUNT: 1; MAXGCOUNT: 1; OUMECLASSIFICATION: [; OUMEMAKER: NAD ¼ºdH; OUMEMAKERKATAMEI: ALF1P05_20A; OUMEPARTTYPE: K; PARTNAME: ALDP112W; VAL1: ALDP112W; VAL3: ALDP112W
STAR1-STAR3 = STAR2: COMPONENTTYPE: 4; PARTNAME: ONEPOINT
DP5 DP6 DP107-DP111 TP3 TP4 = DTP: COMPONENTTYPE: 4; PARTNAME: TP-TH0.8-L1.4
U?#5 = WAKU_DEF100_2021: COMPONENTTYPE: 2; DATE: 2021-06-24; DRAWINGNUMBER: RD034-SCHEMATIC-01; FUNCTION: PFC(1); REVISION: 01; SAVEAREA0: -63393,-16950,474261,314592; SHEETNUMBER: 1/6; TITLE: 100 W Power Supply for LED Lighting; UPDATETIME: 10:53:16
VR1 = DVARA: ADSCNVFLAG: ON; CDMASTERCADCELG: KD1055; COMPCOMMENT: 320VAC ;PANASONIC ;ERZE14A511 ;- ;16.5o~6.8o~20o; COMPONENTTYPE: 4; FNLEADFREETHET1GT2GMCTH1: N_N_N; GCOUNT: 1; MAXGCOUNT: 1; MOUNTINGFORMSMD: SMD; OUMECLASSIFICATION: ƒoƒŠƒXƒ^; OUMEMAKER: NAT ¼ºdíYÆ; OUMEMAKERKATAMEI: ERZVF2M560; OUMEPARTTYPE: RV; PARTNAME: ERZE14A511; VAL1: 320VAC; VAL3: ERZE14A511
C2 C6 C10 = DC: ADSCNVFLAG: ON; ADSCOMPONENTNAME: C_1005; ADSMODELNAME: s_GRM155R61E104KA87D; CAPACITANCETOLE: K; CDMASTERCADCELG: KC0005; COMPCOMMENT: 1000p/10%/25V ;MURATA ;GRM155R61E102KA01 ;1005 ;-; COMPONENTTYPE: 4; FNLEADFREETHET1GT2GMCTH1: N_N_N; GCOUNT: 1; ICX_PART_MODEL: CON_100n; MAXGCOUNT: 1; NOMINALCAPACITA: 100n; OUMECLASSIFICATION: ƒZƒ‰ƒ~ƒbƒNƒRƒ“ƒfƒ“ƒT; OUMEMAKER: MRT ºc»ì; OUMEMAKERKATAMEI: GRM155R61E104KA87D; OUMEPARTTYPE: C; PARTNAME: GRM155R61E102KA01; RATEDVOLTAGE: 25; SIZECODESMD: 1005; VAL1: 1000pF(K); VAL2: 25V; VAL3: GRM155R61E102KA01
C3 = DCP2: COMPCOMMENT: 150Ê/20%/450V ;NICHICON ;LLG2W151MELA25 ;- ;Ó25o~27oCèibvd¬1487mA; COMPONENTTYPE: 4; PARTNAME: LLG2W151MELA25; VAL1: 150uF(M); VAL2: 450V; VAL3: LLG2W151MELA25
C9 = DC: ADSCNVFLAG: ON; ADSCOMPONENTNAME: C_1608; ADSMODELNAME: s_C0603C472K4RACTU; CAPACITANCETOLE: K; CDMASTERCADCELG: KC0008; COMPCOMMENT: 4.7ƒÊ/10%/25V ;TDK ;C1608X5R1E475K080AC ;1608 ;-; COMPONENTTYPE: 4; FNLEADFREETHET1GT2GMCTH1: N_N_N; GCOUNT: 1; ICX_PART_MODEL: CON_4.7n; MAXGCOUNT: 1; NOMINALCAPACITA: 4.7n; OUMECLASSIFICATION: ƒZƒ‰ƒ~ƒbƒNƒRƒ“ƒfƒ“ƒT; OUMEMAKER: KMT PbgGNgjNX; OUMEMAKERKATAMEI: C0603C472K4RACTU; OUMEPARTTYPE: C; PARTNAME: C1608X5R1E475K080AC; RATEDVOLTAGE: 16; SIZECODESMD: 1608; VAL1: 4.7uF(K); VAL2: 25V; VAL3: C1608X5R1E475K080AC
C11 = DC: ADSCNVFLAG: ON; ADSCOMPONENTNAME: C_2012; ADSMODELNAME: s_C2012X5R1E475K085AC; CAPACITANCETOLE: K; CDMASTERCADCELG: KC0006; COMPCOMMENT: 0.56ƒÊ/10%/50V ;KEMET ;C0805C564K5RACTU ;2012 ;-; COMPONENTTYPE: 4; FNLEADFREETHET1GT2GMCTH1: N_N_N; GCOUNT: 1; ICX_PART_MODEL: CON_4.7u; MAXGCOUNT: 1; NOMINALCAPACITA: 4.7u; OUMECLASSIFICATION: ƒZƒ‰ƒ~ƒbƒNƒRƒ“ƒfƒ“ƒT; OUMEMAKER: TDK ‚s‚c‚j; OUMEMAKERKATAMEI: C2012X5R1E475K085AC; OUMEPARTTYPE: C; PARTNAME: C0805C564K5RACTU; RATEDVOLTAGE: 25; SIZECODESMD: 2012; VAL1: 0.56uF(K); VAL2: 50V; VAL3: C0805C564K5RACTU
C12 = DC: ADSCNVFLAG: ON; ADSCOMPONENTNAME: C_1608; ADSMODELNAME: s_GRM1885C1H180JA01D; CAPACITANCETOLE: J; CDMASTERCADCELG: KC0008; COMPCOMMENT: 47p/5%/100V ;MURATA ;GRM1885C2A470JA01D ;1608 ;-; COMPONENTTYPE: 4; FNLEADFREETHET1GT2GMCTH1: N_N_N; GCOUNT: 1; ICX_PART_MODEL: CON_18p; MAXGCOUNT: 1; NOMINALCAPACITA: 18p; OUMECLASSIFICATION: ƒZƒ‰ƒ~ƒbƒNƒRƒ“ƒfƒ“ƒT; OUMEMAKER: MRT ºc»ì; OUMEMAKERKATAMEI: GRM1885C1H180JA01D; OUMEPARTTYPE: C; PARTNAME: GRM1885C2A470JA01D; RATEDVOLTAGE: 50; SIZECODESMD: 1608; VAL1: 47pF(J); VAL2: 100V; VAL3: GRM1885C2A470JA01D
C14 C15 = DC: ADSCNVFLAG: ON; ADSCOMPONENTNAME: C_3216; ADSMODELNAME: s_UMK316BJ475KL-T; CAPACITANCETOLE: K; CDMASTERCADCELG: KC0014; COMPCOMMENT: not mount ;- ;- ;3216 ;-; COMPONENTTYPE: 4; FNLEADFREETHET1GT2GMCTH1: N_N_N; GCOUNT: 1; ICX_PART_MODEL: CON_4.7u; MAXGCOUNT: 1; NOMINALCAPACITA: 4.7u; NOTMOUNT: NOT MOUNT; OUMECLASSIFICATION: ƒZƒ‰ƒ~ƒbƒNƒRƒ“ƒfƒ“ƒT; OUMEMAKER: TYD ‘¾—z—U“d; OUMEMAKERKATAMEI: UMK316BJ475KL-T; OUMEPARTTYPE: C; PARTNAME: C3216; RATEDVOLTAGE: 50; SIZECODESMD: 3216
D1 D105 = DSBD2: COMPCOMMENT: 8A/650V ;TOSHIBA ;TRS8E65F ;TO-220-2L ;-; COMPONENTTYPE: 4; PARTNAME: TRS8E65F; USERCOMPTEXT3: TOSHIBA; VAL1: 8A/650V; VAL3: TRS8E65F
D2 D102-D104 = DSBDC2: COMPCOMMENT: 8A/650V;STMicroelectronics;STPSC8H065B-TR;DPAK@;6.6o~10.1o~2.4o; COMPONENTTYPE: 4; PARTNAME: STPSC8H065B-TR; VAL1: STPSC8H065B-TR; VAL3: STPSC8H065B-TR
D3 D101 D106 D107 = DSBD2: COMPCOMMENT: 1A/30V;TOSHIBA;CUS01(TE85L,Q,M);3-2B1A;2.5o~1.25o~0.6o; COMPONENTTYPE: 4; PARTNAME: CUS01; USERCOMPTEXT3: TOSHIBA; VAL1: CUS01(TE85L,Q,M); VAL3: CUS01(TE85L,Q,M)
D8 D100 = DZD2: COMPCOMMENT: 20V ;TOSHIBA ;CRZ20 ;- ;3.5o~1.6o~0.98o; COMPONENTTYPE: 4; PARTNAME: CRZ20; USERCOMPTEXT3: TOSHIBA; VAL1: CRZ20; VAL3: CRZ20
D9 = DSBD2: COMPCOMMENT: 0.7A/60V ;TOSHIBA ;CUS04 ;- ;2.5o~1.25o~0.6o; COMPONENTTYPE: 4; PARTNAME: CUS04; USERCOMPTEXT3: TOSHIBA; VAL1: CUS04; VAL3: CUS04
IC1 = UCC28051: COMPCOMMENT: UCC28051 ;TI ;UCC28051 ;SOIC-8 ;-; COMPONENTTYPE: 4; PARTNAME: UCC28051D
L1 = PFC3125ER-231K06B-00: COMPCOMMENT: 230ÊH/6.4A ;TDK ;PFC3125ER-231K06B-00 ;- ;26mm~33mm~27mm,'1F0.11111; COMPONENTTYPE: 4
Q1 = DMFNF: COMPCOMMENT: TK290A60Y ;TOSHIBA ;TK290A60Y ;TO-220SIS ;-; COMPONENTTYPE: 4; PARTNAME: TK290A60Y; USERCOMPTEXT3: TOSHIBA; VAL1: TK290A60Y; VAL3: TK290A60Y
R1 = DR: ADSCNVFLAG: ON; ADSCOMPONENTNAME: R_null; ADSMODELNAME: s_ERA3AEB154V; CDMASTERCADCELG: KC0008; COMPCOMMENT: 6.49k/0.1%/0.2W ;PANASONIC ;ERJ-PB3B6491V ;1608 ;-; COMPONENTTYPE: 4; FNLEADFREETHET1GT2GMCTH1: N_N_N; GCOUNT: 1; ICX_PART_MODEL: RES_150k; MAXGCOUNT: 1; MOUNTINGFORMSMD: SMD; NOMINALRESISTAN: 150k; OUMECLASSIFICATION: ÅèïRí; OUMEMAKER: NAE pi\jbNGNgjbNfoCX; OUMEMAKERKATAMEI: ERA3AEB154V; OUMEPARTTYPE: R; PARTNAME: ERJPB3B6491V; POWERRATING: 63m; RESISTANCETOLER: B; SIZECODESMD: 1608; VAL1: 6.49K(B); VAL2: 0.2W; VAL3: ERJ-PB3B6491V
R2 R9 R23 R24 = DR: ADSCNVFLAG: ON; ADSCOMPONENTNAME: R_3216; ADSMODELNAME: s_TSR8GTD471V@KE; CDMASTERCADCELG: CHP003; COMPCOMMENT: 205k/0.1%/0.25W ;PANASONIC ;ERA-8AEB2053V ;3216 ;-; COMPONENTTYPE: 4; FNLEADFREETHET1GT2GMCTH1: N_N_N; GCOUNT: 1; ICX_PART_MODEL: RES_470; MAXGCOUNT: 1; MOUNTINGFORMSMD: SMD; NOMINALRESISTAN: 470; OUMECLASSIFICATION: ÅèïRí; OUMEMAKER: TAT §RÈwHÆ; OUMEMAKERKATAMEI: TSR8GTD471V@KE; OUMEPARTTYPE: R; PARTNAME: ERA8AEB2053V; POWERRATING: 250m; RESISTANCETOLER: D; SIZECODESMD: 3216; VAL1: 205K(B); VAL2: 0.25W; VAL3: ERA-8AEB2053V
R3 = DR: ADSCNVFLAG: ON; ADSCOMPONENTNAME: R_null; ADSMODELNAME: s_ERA3AEB154V; CDMASTERCADCELG: KC0008; COMPCOMMENT: 6.8k/1%/0.1W ;KOA ;RK73H1JTTD6801F ;1608 ;-; COMPONENTTYPE: 4; FNLEADFREETHET1GT2GMCTH1: N_N_N; GCOUNT: 1; ICX_PART_MODEL: RES_150k; MAXGCOUNT: 1; MOUNTINGFORMSMD: SMD; NOMINALRESISTAN: 150k; OUMECLASSIFICATION: ÅèïRí; OUMEMAKER: NAE pi\jbNGNgjbNfoCX; OUMEMAKERKATAMEI: ERA3AEB154V; OUMEPARTTYPE: R; PARTNAME: RK73H1JTTD6801F; POWERRATING: 63m; RESISTANCETOLER: B; SIZECODESMD: 1608; VAL1: 6.8k(F); VAL2: 0.1W; VAL3: RK73H1JTTD6801F
R5 R8 R25 = DR: ADSCNVFLAG: ON; ADSCOMPONENTNAME: R_3216; ADSMODELNAME: s_TSR8GTD471V@KE; CDMASTERCADCELG: CHP003; COMPCOMMENT: 330k/1%/0.25W ;Vishay ;CRCW1206330KFKEA ;3216 ;-; COMPONENTTYPE: 4; FNLEADFREETHET1GT2GMCTH1: N_N_N; GCOUNT: 1; ICX_PART_MODEL: RES_470; MAXGCOUNT: 1; MOUNTINGFORMSMD: SMD; NOMINALRESISTAN: 470; OUMECLASSIFICATION: ÅèïRí; OUMEMAKER: TAT §RÈwHÆ; OUMEMAKERKATAMEI: TSR8GTD471V@KE; OUMEPARTTYPE: R; PARTNAME: CRCW1206330KFKEA; POWERRATING: 250m; RESISTANCETOLER: D; SIZECODESMD: 3216; VAL1: 330k(F); VAL2: 0.25W; VAL3: CRCW1206330KFKEA
R6 = DR: ADSCNVFLAG: ON; ADSCOMPONENTNAME: R_null; ADSMODELNAME: s_ERJ6ENF22R0V; CDMASTERCADCELG: KC0006; COMPCOMMENT: 1‚‹/5%/0.5‚v ;PANASONIC ;ERJ-P06J102V ;2012 ;-; COMPONENTTYPE: 4; FNLEADFREETHET1GT2GMCTH1: N_N_N; GCOUNT: 1; ICX_PART_MODEL: RES_22; MAXGCOUNT: 1; MOUNTINGFORMSMD: SMD; NOMINALRESISTAN: 22; OUMECLASSIFICATION: ÅèïRí; OUMEMAKER: NAE pi\jbNGNgjbNfoCX; OUMEMAKERKATAMEI: ERJ6ENF22R0V; OUMEPARTTYPE: R; PARTNAME: ERJP06J102V; POWERRATING: 125m; RESISTANCETOLER: F; SIZECODESMD: 2012; VAL1: 1k(J); VAL2: 0.5W; VAL3: ERJ-P06J102V
R7 R26 = DR: ADSCNVFLAG: ON; ADSCOMPONENTNAME: R_null; ADSMODELNAME: s_SG732ETTD2R2K; CDMASTERCADCELG: KC0013; COMPCOMMENT: 0.68ƒ¶/1%/1.33W ;PANASONIC ;ERJA1BFR68U ;6432 ;-; COMPONENTTYPE: 4; FNLEADFREETHET1GT2GMCTH1: N_N_N; GCOUNT: 1; ICX_PART_MODEL: RES_2.2; MAXGCOUNT: 1; MOUNTINGFORMSMD: SMD; NOMINALRESISTAN: 2.2; OUMECLASSIFICATION: ÅèïRí; OUMEMAKER: KOA R[A; OUMEMAKERKATAMEI: SG732ETTD2R2K; OUMEPARTTYPE: R; PARTNAME: ERJA1BFR68U; POWERRATING: 330m; RESISTANCETOLER: K; SIZECODESMD: OTHER; VAL1: 0.68(F); VAL2: 1.33W; VAL3: ERJA1BFR68U
R10 = DR: COMPCOMMENT: 47/5%/0.5W ;Panasonic ;ERJP06J470J ;2012 ;-; COMPONENTTYPE: 4; PARTNAME: ERJP06J470V; VAL1: 47(J); VAL2: 0.5W; VAL3: ERJP06J470V
R11 = DR: ADSCNVFLAG: ON; ADSCOMPONENTNAME: R_null; ADSMODELNAME: s_RK73B1ETTP103J; CDMASTERCADCELG: KC0005; COMPCOMMENT: 330/5%/0.1W ;KOA ;RK73B1ETTP331J ;1005 ;-; COMPONENTTYPE: 4; FNLEADFREETHET1GT2GMCTH1: N_N_N; GCOUNT: 1; ICX_PART_MODEL: RES_10k; MAXGCOUNT: 1; MOUNTINGFORMSMD: SMD; NOMINALRESISTAN: 10k; OUMECLASSIFICATION: ÅèïRí; OUMEMAKER: KOA R[A; OUMEMAKERKATAMEI: RK73B1ETTP103J; OUMEPARTTYPE: R; PARTNAME: RK73B1ETTP331J; POWERRATING: 63m; RESISTANCETOLER: J; SIZECODESMD: 1005; VAL1: 330(J); VAL2: 0.1W; VAL3: RK73B1ETTP331J
R12 = DR: ADSCNVFLAG: ON; ADSCOMPONENTNAME: R_null; ADSMODELNAME: s_ERA3AEB154V; CDMASTERCADCELG: KC0008; COMPCOMMENT: 47/5%/0.125W ;KOA ;RK73B1JTTD470J ;1608 ;-; COMPONENTTYPE: 4; FNLEADFREETHET1GT2GMCTH1: N_N_N; GCOUNT: 1; ICX_PART_MODEL: RES_150k; MAXGCOUNT: 1; MOUNTINGFORMSMD: SMD; NOMINALRESISTAN: 150k; OUMECLASSIFICATION: ÅèïRí; OUMEMAKER: NAE pi\jbNGNgjbNfoCX; OUMEMAKERKATAMEI: ERA3AEB154V; OUMEPARTTYPE: R; PARTNAME: RK73B1JTTD470J; POWERRATING: 63m; RESISTANCETOLER: B; SIZECODESMD: 1608; VAL1: 47(J); VAL2: 0.125W; VAL3: RK73B1JTTD470J
R13 = DR: ADSCNVFLAG: ON; ADSCOMPONENTNAME: R_null; ADSMODELNAME: s_RK73B1ETTP103J; CDMASTERCADCELG: KC0005; COMPCOMMENT: 3.3k/0.5%/0.2W ;PANASONIC ;ERJ-PA2D3301X ;1005 ;-; COMPONENTTYPE: 4; FNLEADFREETHET1GT2GMCTH1: N_N_N; GCOUNT: 1; ICX_PART_MODEL: RES_10k; MAXGCOUNT: 1; MOUNTINGFORMSMD: SMD; NOMINALRESISTAN: 10k; OUMECLASSIFICATION: ÅèïRí; OUMEMAKER: KOA R[A; OUMEMAKERKATAMEI: RK73B1ETTP103J; OUMEPARTTYPE: R; PARTNAME: ERJPA2D3301X; POWERRATING: 63m; RESISTANCETOLER: J; SIZECODESMD: 1005; VAL1: 3.3k(D); VAL2: 0.2W; VAL3: ERJ-PA2D3301X
R14 = DR: ADSCNVFLAG: ON; ADSCOMPONENTNAME: R_null; ADSMODELNAME: s_RK73B1ETTP103J; CDMASTERCADCELG: KC0005; COMPCOMMENT: 33k/5%/0.1W ;KOA ;RK73B1ETTP333J ;1005 ;-; COMPONENTTYPE: 4; FNLEADFREETHET1GT2GMCTH1: N_N_N; GCOUNT: 1; ICX_PART_MODEL: RES_10k; MAXGCOUNT: 1; MOUNTINGFORMSMD: SMD; NOMINALRESISTAN: 10k; OUMECLASSIFICATION: ÅèïRí; OUMEMAKER: KOA R[A; OUMEMAKERKATAMEI: RK73B1ETTP103J; OUMEPARTTYPE: R; PARTNAME: RK73B1ETTP333J; POWERRATING: 63m; RESISTANCETOLER: J; SIZECODESMD: 1005; VAL1: 33k(J); VAL2: 0.1W; VAL3: RK73B1ETTP333J
R17 = DR: ADSCNVFLAG: ON; ADSCOMPONENTNAME: R_null; ADSMODELNAME: s_ERA3AEB154V; CDMASTERCADCELG: KC0008; COMPCOMMENT: 10k/5%/0.1W ;KOA ;RK73B1JTTD103J ;1608 ;; COMPONENTTYPE: 4; FNLEADFREETHET1GT2GMCTH1: N_N_N; GCOUNT: 1; ICX_PART_MODEL: RES_150k; MAXGCOUNT: 1; MOUNTINGFORMSMD: SMD; NOMINALRESISTAN: 150k; OUMECLASSIFICATION: ÅèïRí; OUMEMAKER: NAE pi\jbNGNgjbNfoCX; OUMEMAKERKATAMEI: ERA3AEB154V; OUMEPARTTYPE: R; PARTNAME: RK73B1JTTD103J; POWERRATING: 63m; RESISTANCETOLER: B; SIZECODESMD: 1608; VAL1: 10k(J); VAL2: 0.1W; VAL3: RK73B1JTTD103J
R18 = DR: ADSCNVFLAG: ON; ADSCOMPONENTNAME: R_null; ADSMODELNAME: s_ERA3AEB154V; CDMASTERCADCELG: KC0008; COMPCOMMENT: 187k/0.1%/0.25W ;PANASONIC ;ERA-8AEB1873V ;3216 ;-; COMPONENTTYPE: 4; FNLEADFREETHET1GT2GMCTH1: N_N_N; GCOUNT: 1; ICX_PART_MODEL: RES_150k; MAXGCOUNT: 1; MOUNTINGFORMSMD: SMD; NOMINALRESISTAN: 150k; OUMECLASSIFICATION: ÅèïRí; OUMEMAKER: NAE pi\jbNGNgjbNfoCX; OUMEMAKERKATAMEI: ERA3AEB154V; OUMEPARTTYPE: R; PARTNAME: ERA8AEB1873V; POWERRATING: 63m; RESISTANCETOLER: B; SIZECODESMD: 1608; VAL1: 187k(B); VAL2: 0.25W; VAL3: ERA-8AEB1873V
R19-R22 = DR: ADSCNVFLAG: ON; ADSCOMPONENTNAME: R_null; ADSMODELNAME: s_SCR35 471JV PB_F_; CDMASTERCADCELG: DR903A; COMPCOMMENT: not mount;- ;0.5W ÎT[W@400V ;3225 ;-; COMPONENTTYPE: 4; FNLEADFREETHET1GT2GMCTH1: N_N_N; GCOUNT: 1; ICX_PART_MODEL: RES_470; MAXGCOUNT: 1; MOUNTINGFORMSMD: SMD; NOMINALRESISTAN: 470; NOTMOUNT: NOT MOUNT; OUMECLASSIFICATION: ÅèïRí; OUMEMAKER: HDK k¤dCHÆ; OUMEMAKERKATAMEI: SCR35 471JV PB(F); OUMEPARTTYPE: R; PARTNAME: R3225; POWERRATING: 500m; RESISTANCETOLER: J; SIZECODESMD: 3225
R139 = DR: ADSCNVFLAG: ON; ADSCOMPONENTNAME: R_3216; ADSMODELNAME: s_TSR8GTD471V@KE; CDMASTERCADCELG: CHP003; COMPCOMMENT: 0/2A;KOA;RK73Z2BTTD;3216;-; COMPONENTTYPE: 4; FNLEADFREETHET1GT2GMCTH1: N_N_N; GCOUNT: 1; ICX_PART_MODEL: RES_470; MAXGCOUNT: 1; MOUNTINGFORMSMD: SMD; NOMINALRESISTAN: 470; OUMECLASSIFICATION: ÅèïRí; OUMEMAKER: TAT §RÈwHÆ; OUMEMAKERKATAMEI: TSR8GTD471V@KE; OUMEPARTTYPE: R; PARTNAME: RK73Z2BTTD; POWERRATING: 250m; RESISTANCETOLER: D; SIZECODESMD: 3216; VAL1: 0; VAL2: 2A; VAL3: RK73Z2BTTD
U?#4 = WAKU_DEF100_2021: COMPONENTTYPE: 2; DATE: 2021-06-24; DRAWINGNUMBER: RD034-SCHEMATIC-01; FUNCTION: PFC(2); PAGENUMBER: 4; REVISION: 01; SAVEAREA0: -63393,-16950,474261,314592; SHEETNUMBER: 2/6; TITLE: 100 W Power Supply for LED Lighting; UPDATETIME: 10:53:16
C100 = DC: COMPCOMMENT: 0.022u/10%/25V;Kyocera;CM05X5R223K25AB;1005;-; COMPONENTTYPE: 4; PARTNAME: CM05; VAL1: 0.022uF(K); VAL2: 25V; VAL3: CM05X5R223K25AB
C107 = DC: COMPCOMMENT: 3216; COMPONENTTYPE: 4; PARTNAME: GRM31BR72J682KW01L; VAL1: 6800pF(K); VAL2: 630V; VAL3: GRM31BR72J682KW01L
C111 C121 = DCP2: COMPCOMMENT: 100Ê/20%/160V;PANASONIC;EEUEE2C101;³12.5o~25o; COMPONENTTYPE: 4; PARTNAME: EEUEE2C101; VAL1: 100uF(M); VAL2: 160V; VAL3: EEUEE2C101
C112 C122 = DC: COMPCOMMENT: 3216; COMPONENTTYPE: 4; PARTNAME: GRM31CR72E104KW03L; VAL1: 0.1uF(K); VAL2: 250V; VAL3: GRM31CR72E104KW03L
C124 C125 = DC: ADSCNVFLAG: ON; ADSCOMPONENTNAME: C_1005; ADSMODELNAME: s_GRM155R61E104KA87D; CAPACITANCETOLE: K; CDMASTERCADCELG: KC0005; COMPCOMMENT: 3225; COMPONENTTYPE: 4; FNLEADFREETHET1GT2GMCTH1: N_N_N; GCOUNT: 1; ICX_PART_MODEL: CON_100n; MAXGCOUNT: 1; NOMINALCAPACITA: 100n; OUMECLASSIFICATION: ƒZƒ‰ƒ~ƒbƒNƒRƒ“ƒfƒ“ƒT; OUMEMAKER: MRT ºc»ì; OUMEMAKERKATAMEI: GRM155R61E104KA87D; OUMEPARTTYPE: C; PARTNAME: GMK325BJ106KN-T; RATEDVOLTAGE: 25; SIZECODESMD: 1005; VAL1: 10uF(K); VAL2: 35V; VAL3: GMK325BJ106KN-T
DP112 = DTP: COMPCOMMENT: ³1.8oÌX[z[Æ·é; COMPONENTTYPE: 4; FUNCTION: VOUT+; PARTNAME: TP-TH1.8-L3.5
DP113 = DTP: COMPCOMMENT: ³1.8oÌX[z[Æ·é; COMPONENTTYPE: 4; FUNCTION: VOUT-; PARTNAME: TP-TH1.8-L3.5
IC100 = UCC28600: COMPCOMMENT: UCC28600;TI;UCC28600;SOIC-8;-; COMPONENTTYPE: 4; PARTNAME: UCC28600DR
Q100 = DTRP: COMPCOMMENT: 2SA1588;TOSHIBA;2SA1588;SC-70;-; COMPONENTTYPE: 4; PARTNAME: 2SA1588; USERCOMPTEXT3: TOSHIBA; VAL1: 2SA1588; VAL3: 2SA1588
Q101 = DMFNF: COMPCOMMENT: TK290A65Y;TOSHIBA;TK290A65Y;TO-220SIS;-; COMPONENTTYPE: 4; PARTNAME: TK290A65Y; USERCOMPTEXT3: TOSHIBA; VAL1: TK290A65Y; VAL3: TK290A65Y
R100 = DR: ADSCNVFLAG: ON; ADSCOMPONENTNAME: R_null; ADSMODELNAME: s_RK73B1ETTP100J; CDMASTERCADCELG: KC0005; COMPCOMMENT: 10/5%/0.1W;KOA;RK73B1ETTP100J;1005; COMPONENTTYPE: 4; FNLEADFREETHET1GT2GMCTH1: N_N_N; GCOUNT: 1; ICX_PART_MODEL: RES_10; MAXGCOUNT: 1; MOUNTINGFORMSMD: SMD; NOMINALRESISTAN: 10; OUMECLASSIFICATION: ÅèïRí; OUMEMAKER: KOA R[A; OUMEMAKERKATAMEI: RK73B1ETTP100J; OUMEPARTTYPE: R; PARTNAME: RK73B1ETTP100J; POWERRATING: 63m; RESISTANCETOLER: J; SIZECODESMD: 1005; VAL1: 10(J); VAL2: 0.1W; VAL3: RK73B1ETTP100J
R101 = DR: ADSCNVFLAG: ON; ADSCOMPONENTNAME: R_null; ADSMODELNAME: s_RK73B1ETTP681J; CDMASTERCADCELG: KC0005; COMPCOMMENT: 680/5%/0.1W;KOA;RK73B1ETTP681J;1005;-; COMPONENTTYPE: 4; FNLEADFREETHET1GT2GMCTH1: N_N_N; GCOUNT: 1; ICX_PART_MODEL: RES_680; MAXGCOUNT: 1; MOUNTINGFORMSMD: SMD; NOMINALRESISTAN: 680; OUMECLASSIFICATION: ÅèïRí; OUMEMAKER: KOA R[A; OUMEMAKERKATAMEI: RK73B1ETTP681J; OUMEPARTTYPE: R; PARTNAME: RK73B1ETTP681J; POWERRATING: 63m; RESISTANCETOLER: J; SIZECODESMD: 1005; VAL1: 680(J); VAL2: 0.1W; VAL3: RK73B1ETTP681J
R102 = DR: COMPCOMMENT: 3.3k/5%/0.2W;PANASONIC;ERJPA2J332X;1005;-; COMPONENTTYPE: 4; PARTNAME: ERJPA2J332X; VAL1: 3.3k(J); VAL2: 0.2W; VAL3: ERJPA2J332X
R105-R107 = DR: COMPCOMMENT: 3216; COMPONENTTYPE: 4; PARTNAME: ERJ8GEYJ564V; VAL1: 560k(J); VAL2: 0.25W; VAL3: ERJ-8GEYJ564V
R108 = DR: COMPCOMMENT: 17.8k/1%/0.1W;PANASONIC;ERJ2RKF1782X;1005;-; COMPONENTTYPE: 4; PARTNAME: ERJ2RKF1782X; VAL1: 17.8k(F); VAL2: 0.1W; VAL3: ERJ2RKF1782X
R110 = DR: COMPCOMMENT: 590/1%/0.1W;KOA;RK73H1ETTP5900F;1005;-; COMPONENTTYPE: 4; PARTNAME: RK73H1ETTP5900F; VAL1: 590(F); VAL2: 0.1W; VAL3: RK73H1ETTP5900F
R111 R112 = DR: ADSCNVFLAG: ON; ADSCOMPONENTNAME: R_null; ADSMODELNAME: s_ERA3AEB154V; CDMASTERCADCELG: KC0008; COMPCOMMENT: 10/5%/0.125W ;KOA ;RK73B1JTTD100J ;1608 ;-; COMPONENTTYPE: 4; FNLEADFREETHET1GT2GMCTH1: N_N_N; GCOUNT: 1; ICX_PART_MODEL: RES_150k; MAXGCOUNT: 1; MOUNTINGFORMSMD: SMD; NOMINALRESISTAN: 150k; OUMECLASSIFICATION: ÅèïRí; OUMEMAKER: NAE pi\jbNGNgjbNfoCX; OUMEMAKERKATAMEI: ERA3AEB154V; OUMEPARTTYPE: R; PARTNAME: RK73B1JTTD100J; POWERRATING: 63m; RESISTANCETOLER: B; SIZECODESMD: 1608; VAL1: 10(J); VAL2: 0.125W; VAL3: RK73B1JTTD100J
R114 = DR: ADSCNVFLAG: ON; ADSCOMPONENTNAME: R_null; ADSMODELNAME: s_RK73B1ETTP103J; CDMASTERCADCELG: KC0005; COMPCOMMENT: 10k/5%/0.1W;KOA;RK73B1ETTP103J;1005;1o~0.5o~0.35o; COMPONENTTYPE: 4; FNLEADFREETHET1GT2GMCTH1: N_N_N; GCOUNT: 1; ICX_PART_MODEL: RES_10k; MAXGCOUNT: 1; MOUNTINGFORMSMD: SMD; NOMINALRESISTAN: 10k; OUMECLASSIFICATION: ÅèïRí; OUMEMAKER: KOA R[A; OUMEMAKERKATAMEI: RK73B1ETTP103J; OUMEPARTTYPE: R; PARTNAME: RK73B1ETTP103J; POWERRATING: 63m; RESISTANCETOLER: J; SIZECODESMD: 1005; VAL1: 10k(J); VAL2: 0.1W; VAL3: RK73B1ETTP103J
R117 R137 = DR: COMPCOMMENT: 0.47/1%/0.5W;KOA;SR732ARTTDR470F;2012;-; COMPONENTTYPE: 4; PARTNAME: SR732ARTTDR470F; VAL1: 0.47(F); VAL2: 0.5W; VAL3: SR732ARTTDR470F
R118 = DR: COMPCOMMENT: 2012; COMPONENTTYPE: 4; PARTNAME: ERJP6WF13R0V; VAL1: 13(F); VAL2: 0.5W; VAL3: ERJP6WF13R0V
R119 = DR: COMPCOMMENT: 1608; COMPONENTTYPE: 4; PARTNAME: RK73H1JRTTD4702F; VAL1: 47k(F); VAL2: 0.1W; VAL3: RK73H1JRTTD4702F
R120 R138 = DR: COMPCOMMENT: 6.2k/5%/20W;NIKKOHM;RNP-10SA6K2JZ03;TO126;-; COMPONENTTYPE: 4; PARTNAME: RNP-10SA6K2JZ03; VAL1: 6.2k(J); VAL2: 20W; VAL3: RNP-10SA6K2JZ03
R121 = DR: COMPCOMMENT: 2012; COMPONENTTYPE: 4; PARTNAME: ERJUP6F5603V; VAL1: 560k(F); VAL2: 0.5W; VAL3: ERJUP6F5603V
R132 = DR: ADSCNVFLAG: ON; ADSCOMPONENTNAME: R_null; ADSMODELNAME: s_RK73H1JTTD4700F; CDMASTERCADCELG: KC0008; COMPCOMMENT: 470/1%/0.125W;KOA;RK73H1JTTD4700F;1608;-; COMPONENTTYPE: 4; FNLEADFREETHET1GT2GMCTH1: N_N_N; GCOUNT: 1; ICX_PART_MODEL: RES_470; MAXGCOUNT: 1; MOUNTINGFORMSMD: SMD; NOMINALRESISTAN: 470; OUMECLASSIFICATION: ÅèïRí; OUMEMAKER: KOA R[A; OUMEMAKERKATAMEI: RK73H1JTTD4700F; OUMEPARTTYPE: R; PARTNAME: RK73H1JTTD4700F; POWERRATING: 100m; RESISTANCETOLER: F; SIZECODESMD: 1608; VAL1: 470(F); VAL2: 0.125W; VAL3: RK73H1JTTD4700F
R133 R134 = DR: COMPCOMMENT: 3225; COMPONENTTYPE: 4; PARTNAME: ERJ14BQF1R0U; VAL1: 1(F); VAL2: 0.5W; VAL3: ERJ14BQF1R0U
R140-R142 = DR: ADSCNVFLAG: ON; ADSCOMPONENTNAME: R_3216; ADSMODELNAME: s_TSR8GTD471V@KE; CDMASTERCADCELG: CHP003; COMPCOMMENT: 1608; COMPONENTTYPE: 4; FNLEADFREETHET1GT2GMCTH1: N_N_N; GCOUNT: 1; ICX_PART_MODEL: RES_470; MAXGCOUNT: 1; MOUNTINGFORMSMD: SMD; NOMINALRESISTAN: 470; OUMECLASSIFICATION: ÅèïRí; OUMEMAKER: TAT §RÈwHÆ; OUMEMAKERKATAMEI: TSR8GTD471V@KE; OUMEPARTTYPE: R; PARTNAME: RK73Z1JTTD; POWERRATING: 250m; RESISTANCETOLER: D; SIZECODESMD: 3216; VAL1: 0; VAL2: 1A; VAL3: RK73Z1JTTD
R145 = DR: COMPCOMMENT: 2012; COMPONENTTYPE: 4; NOTMOUNT: NOT MOUNT; PARTNAME: R2125
T1 = TRANS1: COMPCOMMENT: TRANS1;-;-;-;-; COMPONENTTYPE: 4; PARTNAME: EER28LH; VAL1: Y18T210-61B; VAL3: Y18T210-61B
U?#3 = WAKU_DEF100_2021: COMPONENTTYPE: 2; DATE: 2021-06-24; DRAWINGNUMBER: RD034-SCHEMATIC-01; FUNCTION: FLYBACK(1); PAGENUMBER: 5; REVISION: 01; SAVEAREA0: -63393,-16950,474261,314592; SHEETNUMBER: 3/6; TITLE: 100 W Power Supply for LED Lighting; UPDATETIME: 10:53:16
C109 = DC: COMPCOMMENT: 470p/10%/250VAC;Murata;DE1B3KX471KA4BN01F; COMPONENTTYPE: 4; PARTNAME: DE1B3KX471KA4BN01F; VAL1: 470pF(K); VAL2: 250VAC; VAL3: DE1B3KX471KA4BN01F
C113 = DC: COMPCOMMENT: 1608; COMPONENTTYPE: 4; PARTNAME: TMK107BJ104KAHT; VAL1: 0.1uF(K); VAL2: 25V; VAL3: TMK107BJ104KAHT
C114 = DC: COMPCOMMENT: 1608; COMPONENTTYPE: 4; PARTNAME: GRM188C81E105KAADD; VAL1: 1uF(K); VAL2: 25V; VAL3: GRM188C81E105KAADD
C120 = DC: COMPCOMMENT: not mount;-;-;1608;-; COMPONENTTYPE: 4; NOTMOUNT: NOT MOUNT; PARTNAME: C1608; VAL1: not mount; VAL3: not mount
DS100 = TLP383: COMPCOMMENT: TLP383;TOSHIBA;TLP383;11-3C1;10o~3.84o~2.1o; COMPONENTTYPE: 4; USERCOMPTEXT3: TOSHIBA
IC103 = NCV20071SN2T1G: COMPCOMMENT: NCV20071SN2T1G;ON Semiconductor;NCV20071SN2T1G;TSOP-5;3.15o~1.65o~1o; COMPONENTTYPE: 4
IC104 = TL431AIDBZR: COMPCOMMENT: TL431AIDBZR;TI;TL431AIDBZR;SOT-23;2.92o~1.3o~1o; COMPONENTTYPE: 4
R122 = DR: COMPCOMMENT: 330/5%/0.125W;KOA;RK73B1JTTD101J;1608;-; COMPONENTTYPE: 4; NOTMOUNT: MOUNT; PARTNAME: RK73B1JTTD331J; VAL1: 330(J); VAL2: 0.125W; VAL3: RK73B1JTTD331J
R126 = DR: COMPCOMMENT: 1608; COMPONENTTYPE: 4; PARTNAME: ERA3AEB154V; VAL1: 150k(B); VAL2: 0.1W; VAL3: ERA3AEB154V
R127 R128 = DR: COMPCOMMENT: 2012; COMPONENTTYPE: 4; PARTNAME: ERJP06J202V; VAL1: 2k(J); VAL2: 0.5W; VAL3: ERJP06J202V
R135 = DR: COMPCOMMENT: 120k/0.1%/0.1W;PANASONIC;ERA3AEB124V;1608;-; COMPONENTTYPE: 4; PARTNAME: ERA3AEB124V; VAL1: 120k(B); VAL2: 0.1W; VAL3: ERA3AEB124V
R136 = DR: COMPCOMMENT: 31.6k/0.1%/0.063W;PANASONIC;ERA2AEB3162X;1005;-; COMPONENTTYPE: 4; PARTNAME: ERA2AEB3162X; VAL1: 31.6k(B); VAL2: 0.063W; VAL3: ERA2AEB3162X
U?#2 = WAKU_DEF100_2021: COMPONENTTYPE: 2; DATE: 2021-06-24; DRAWINGNUMBER: RD034-SCHEMATIC-01; FUNCTION: FLYBACK(2); PAGENUMBER: 6; REVISION: 01; SAVEAREA0: -63393,-16950,474261,314592; SHEETNUMBER: 4/6; TITLE: 100 W Power Supply for LED Lighting; UPDATETIME: 10:53:16
C102 C118 = DC: COMPCOMMENT: 2012; COMPONENTTYPE: 4; PARTNAME: C2012X5R1E106K125AB; VAL1: 10uF(K); VAL2: 25V; VAL3: C2012X5R1E106K125AB
C103 C117 = DC: COMPCOMMENT: 1608; COMPONENTTYPE: 4; PARTNAME: GRM1885C2A5R0CA01D; VAL1: 5pF(C); VAL2: 100V; VAL3: GRM1885C2A5R0CA01D
C104 C115 = DC: COMPCOMMENT: 0.01ƒÊ/10%/100V;TDK;C1005X7S2A103K050BB;1005;-; COMPONENTTYPE: 4; PARTNAME: C1005X7S2A103K050BB; VAL1: 0.01uF(K); VAL2: 100V; VAL3: C1005X7S2A103K050BB
C105 C116 = DC: COMPCOMMENT: 2012; COMPONENTTYPE: 4; PARTNAME: C0805C563K1RACTU; VAL1: 0.056uF(K); VAL2: 100V; VAL3: C0805C563K1RACTU
C106 C110 = DC: COMPCOMMENT: 2012; COMPONENTTYPE: 4; PARTNAME: C2012X7S2A105K125AE; VAL1: 1uF(K); VAL2: 100V; VAL3: C2012X7S2A105K125AE
IC101 IC102 = TPS54061DRB2: COMPCOMMENT: TPS54061DRB;TI;TPS54061DRB;VSON-8 DRB;-; COMPONENTTYPE: 4; PARTNAME: TPS54061DRB; VAL1: TPS54061DRB; VAL3: TPS54061DRB
L100 L101 = DL1D: COMPCOMMENT: 150Ê/130mA;Murata Power Solutions;82154C;-;2.5o~3.2o~2o; COMPONENTTYPE: 4; PARTNAME: 82154C; VAL1: 150uH(K); VAL2: 130mA; VAL3: 82154C
R103 = DR: COMPCOMMENT: 200k/0.1%/0.1W;SUSUMU;RG1608P-204-B;1608;-; COMPONENTTYPE: 4; PARTNAME: RG1608P-204-B; VAL1: 200k(B); VAL2: 0.1W; VAL3: RG1608P-204-B
R104 R131 = DR: COMPCOMMENT: 1608; COMPONENTTYPE: 4; PARTNAME: MCR03EZPFX1002; VAL1: 10k(F); VAL2: 0.1W; VAL3: MCR03EZPFX1002
R109 R129 = DR: COMPCOMMENT: 2012; COMPONENTTYPE: 4; PARTNAME: ERJPB6B6203V; VAL1: 620k(B); VAL2: 0.25W; VAL3: ERJPB6B6203V
R113 R125 = DR: COMPCOMMENT: 2012; COMPONENTTYPE: 4; PARTNAME: ERA6AEB4643V; VAL1: 464k(B); VAL2: 0.125W; VAL3: ERA6AEB4643V
R115 = DR: ADSCNVFLAG: ON; ADSCOMPONENTNAME: R_null; ADSMODELNAME: s_RK73H1ETTP6202F; CDMASTERCADCELG: KC0005; COMPCOMMENT: 620k/1%/0.1W;KOA;RK73H1ETTP6203F;1005;-; COMPONENTTYPE: 4; FNLEADFREETHET1GT2GMCTH1: N_N_N; GCOUNT: 1; ICX_PART_MODEL: RES_62k; MAXGCOUNT: 1; MOUNTINGFORMSMD: SMD; NOMINALRESISTAN: 62k; OUMECLASSIFICATION: ÅèïRí; OUMEMAKER: KOA R[A; OUMEMAKERKATAMEI: RK73H1ETTP6202F; OUMEPARTTYPE: R; PARTNAME: RK73H1ETTP6203F; POWERRATING: 63m; RESISTANCETOLER: F; SIZECODESMD: 1005; VAL1: 620k(F); VAL2: 0.1W; VAL3: RK73H1ETTP6203F
R116 = DR: ADSCNVFLAG: ON; ADSCOMPONENTNAME: R_null; ADSMODELNAME: s_RK73H1ETTP4301F; CDMASTERCADCELG: KC0005; COMPCOMMENT: 43k/1%/0.1W;KOA;RK73H1ETTP4302F;1005;-; COMPONENTTYPE: 4; FNLEADFREETHET1GT2GMCTH1: N_N_N; GCOUNT: 1; ICX_PART_MODEL: RES_4.3k; MAXGCOUNT: 1; MOUNTINGFORMSMD: SMD; NOMINALRESISTAN: 4.3k; OUMECLASSIFICATION: ÅèïRí; OUMEMAKER: KOA R[A; OUMEMAKERKATAMEI: RK73H1ETTP4301F; OUMEPARTTYPE: R; PARTNAME: RK73H1ETTP4302F; POWERRATING: 63m; RESISTANCETOLER: F; SIZECODESMD: 1005; VAL1: 43k(F); VAL2: 0.1W; VAL3: RK73H1ETTP4302F
R123 = DR: ADSCNVFLAG: ON; ADSCOMPONENTNAME: R_null; ADSMODELNAME: s_RK73H1ETTP6202F; CDMASTERCADCELG: KC0005; COMPCOMMENT: 62k/1%/0.1W;KOA;RK73H1ETTP6202F;1005;-; COMPONENTTYPE: 4; FNLEADFREETHET1GT2GMCTH1: N_N_N; GCOUNT: 1; ICX_PART_MODEL: RES_62k; MAXGCOUNT: 1; MOUNTINGFORMSMD: SMD; NOMINALRESISTAN: 62k; OUMECLASSIFICATION: ÅèïRí; OUMEMAKER: KOA R[A; OUMEMAKERKATAMEI: RK73H1ETTP6202F; OUMEPARTTYPE: R; PARTNAME: RK73H1ETTP6202F; POWERRATING: 63m; RESISTANCETOLER: F; SIZECODESMD: 1005; VAL1: 62k(F); VAL2: 0.1W; VAL3: RK73H1ETTP6202F
R124 = DR: ADSCNVFLAG: ON; ADSCOMPONENTNAME: R_null; ADSMODELNAME: s_RK73H1ETTP4301F; CDMASTERCADCELG: KC0005; COMPCOMMENT: 4.3k/1%/0.1W;KOA;RK73H1ETTP4301F;1005;-; COMPONENTTYPE: 4; FNLEADFREETHET1GT2GMCTH1: N_N_N; GCOUNT: 1; ICX_PART_MODEL: RES_4.3k; MAXGCOUNT: 1; MOUNTINGFORMSMD: SMD; NOMINALRESISTAN: 4.3k; OUMECLASSIFICATION: ÅèïRí; OUMEMAKER: KOA R[A; OUMEMAKERKATAMEI: RK73H1ETTP4301F; OUMEPARTTYPE: R; PARTNAME: RK73H1ETTP4301F; POWERRATING: 63m; RESISTANCETOLER: F; SIZECODESMD: 1005; VAL1: 4.3k(F); VAL2: 0.1W; VAL3: RK73H1ETTP4301F
R130 = DR: COMPCOMMENT: 1608; COMPONENTTYPE: 4; PARTNAME: CPF0603B215KE1; VAL1: 215k(B); VAL2: 0.063W; VAL3: CPF0603B215KE1
U?#1 = WAKU_DEF100_2021: COMPONENTTYPE: 2; DATE: 2021-06-24; DRAWINGNUMBER: RD034-SCHEMATIC-01; FUNCTION: FLYBACK(3); PAGENUMBER: 7; REVISION: 01; SAVEAREA0: -63393,-16950,474261,314592; SHEETNUMBER: 5/6; TITLE: 100 W Power Supply for LED Lighting; UPDATETIME: 10:53:16
E1 = DHS1: COMPCOMMENT: 1~40~31.1; COMPONENTTYPE: 4; PARTNAME: HEAT-SINK-P1; VAL1: DD1807941_P1; VAL3: DD1807941_P1
E2 E4 = DHS1: COMPCOMMENT: 1~40~31.1; COMPONENTTYPE: 4; PARTNAME: HEAT-SINK-P2; VAL1: DD1807941_P2; VAL3: DD1807941_P2
E3 = DHS1: COMPCOMMENT: 12~73~28.5; COMPONENTTYPE: 4; PARTNAME: SNUBBER-HS; VAL1: DD1808663; VAL3: DD1808663
U?#6 = WAKU_DEF100_2021: COMPONENTTYPE: 2; DATE: 2021-06-24; DRAWINGNUMBER: RD034-SCHEMATIC-01; FUNCTION: HEAT_SHINK; PAGENUMBER: 8; REVISION: 01; SAVEAREA0: -63393,-16950,474261,314592; SHEETNUMBER: 6/6; TITLE: 100 W Power Supply for LED Lighting; UPDATETIME: 10:53:16

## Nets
PGNDA: C3.2 C5.1 C13.1 C109.2 C126.1 C127.1 D4.4 D10.K L1.1 R6.1 R7.1 R17.2 R20.1 R22.1 R26.1 R114.1 R117.1 R119.1 R137.1 RY1.1 STAR1.1 STAR2.2 T1.6 TP4.1
PGNDB: C109.1 C111.2 C112.1 C119.1 C121.2 C122.1 C123.1 IC103.2(VSS) IC104.3(ANODE) R133.1 R134.1 R136.2 STAR3.2 T1.7
S18V: C118.2 C123.2 IC103.5(VDD) L101.2 R127.1 R128.1 R142.2
$BN000001: R146.1 R147.2
$BN000002: R147.1 R148.2
$BN000003: R148.1 R149.2
FLYBACK_DGNDA: C100.1 C101.1 C102.1 C103.1 C105.1 C106.1 C108.1 C124.1 C125.1 D100.A DS100.4 IC100.4(GND) IC101.7(GND) IC101.9(NC) R104.1 R108.1 R113.1 R116.1 STAR1.2
FLYBACK_DGNDB: C110.1 C116.1 C117.1 C118.1 IC102.7(GND) IC102.9(NC) R124.1 R125.1 R131.1 STAR3.1
P16R8V: C102.2 D106.A D107.A DP108.1 L100.2 R141.2
PAW: C106.2 D102.K DP107.1 IC101.2(VIN) R115.2
PFB: C108.2 DS100.6 IC100.2(FB)
PFC_DGNDA: C1.1 C2.1 C6.1 C10.1 C11.1 C12.1 D8.A IC1.6(GND) R1.1 R3.1 R13.1 STAR2.1
PFC_IN: C5.2 C126.2 C127.2 D2.A D4.1 L1.8 R8.2 TP3.1
PFC_OUT: C3.1 D1.K D2.K DP9.1 DP103.1 R105.1 R118.2 R120.2 R138.2 R139.2 R145.2 T1.1
PFC_VCC: C1.2 D8.K DP109.1 IC1.8(VCC) R16.2 R100.1
SAW: C110.2 D104.K DP111.1 IC102.2(VIN) R123.2
SFB: C119.2 IC103.3(IN+) R132.1
SIG5: C100.2 IC100.1(SS)
SIG6: Q100.C R100.2
SIG13: Q100.B R101.1 R102.1
SIG14: IC100.8(STATUS) R102.2
SIG17: D101.A R111.1
SIG18: D101.K IC100.5(OUT) R112.1
SIG19: DP105.1 Q101.G R111.2 R112.2 R114.2
SIG21: DP106.1 Q101.S R110.2 R117.2 R137.2
SIG24: R106.1 R107.1
SIG25: R105.2 R106.2
SIG27: C107.2 R118.1 R145.1
SIG30: D102.A R121.2 T1.4
SIG36: C111.1 C112.2 C121.1 C122.2 D105.K DP110.1 DP112.1
SIG38: D105.A T1.12
SIG39: D104.A T1.9 T1.10
SIG46: IC100.7(OVP) R119.2 R121.1
SIG47: D103.A DP104.1 Q101.D T1.3
SIG48: DP1.1 F1.1
SIG50: D10.A D11.A
SIG56: C4.2 F1.2 L2.2 VR1.2
SIG57: C4.1 DP2.1 DP11.1 L2.1 VR1.1
SIG102: C113.2 DS100.3 IC104.1(CATHODE) R122.1 R126.1
SIG104: DS100.1 R122.2 R127.2 R128.2
SIG108: C114.2 R126.2
SIG109: C113.1 C114.1 C120.2 IC103.1(OUT) IC104.2(REF) R135.1
SIG114: C120.1 IC103.4(IN-) R135.2 R136.1
SIG116: C104.1 IC101.8(PH) L100.1
SIG118: C105.2 R109.1
SIG120: IC101.3(EN) R115.1 R116.2
SIG121: C103.2 IC101.6(COMP) R109.2
SIG122: IC101.5(VSENSE) R103.1 R104.2
SIG124: IC101.4(RT/CLK) R113.2
SIG125: C104.2 IC101.1(BOOT)
SIG126: IC102.4(RT/CLK) R125.2
SIG128: C117.2 IC102.6(COMP) R129.2
SIG129: IC102.3(EN) R123.1 R124.2
SIG131: C116.2 R129.1
SIG132: C115.2 IC102.1(BOOT)
SIG133: IC102.5(VSENSE) R130.1 R131.2
SIG135: C115.1 IC102.8(PH) L101.1
SIG136: R5.1 R25.2
SIG137: R5.2 R8.1
SIG138: C9.1 R13.2
SIG141: C15.1 R19.2 R21.2
SIG142: C9.2 C11.2 IC1.2(COMP)
SIG143: C2.2 IC1.3(MULTIN) R3.2 R25.1
SIG145: D3.A R12.1
SIG146: D3.K IC1.7(DRV) R10.1
SIG147: DP6.1 Q1.G R10.2 R12.2 R17.1
SIG148: C14.1 C15.2
SIG149: C14.2 D1.A DP7.1 L1.6 Q1.D
SIG151: DP8.1 Q1.S R7.2 R11.2 R26.2
SIG152: C10.2 IC1.4(CS) R11.1
SIG153: C12.2 IC1.5(ZCD) R14.2
SIG156: R2.1 R9.2
SIG160: C6.2 IC1.1(VO_SNS) R1.2 R18.1
SIG162: D9.K R6.2
SIG163: D9.A DP5.1 L1.5 R14.1
SIG166: R23.1 R24.2
SIG167: R18.2 R24.1
SIG178: C13.2 D11.K R16.1 RY1.2
SIG179: R19.1 R20.2 R21.1 R22.2
SIG187: R2.2 R139.1
SIG188: R132.2 R140.1
SIG189: R103.2 R141.1
SIG190: R130.2 R142.1
SIG193: DP113.1 R133.2 R134.2 R140.2
SIG201: C107.1 D103.K R120.1 R138.1
SIG204: D4.3 R15.2 R146.2 RY1.3
SIG209: D107.K Q100.E R101.2
SIG210: C101.2 C124.2 C125.2 D100.K D106.K IC100.6(VDD) R107.2
SIG211: IC100.3(CS) R108.2 R110.1
SIG212: R9.1 R23.2
SIG213: C8.2 L2.3 R15.1 RY1.4
SIG214: C8.1 D4.2 L2.4 R149.1

Not connected (* = marked no-connect by the designer): D2 NC; D102 NC; D103 NC; D104 NC; E1 101 102; E2 101 102; E3 101 102; E4 101 102; L1 3 7; T1 2 5 8 11

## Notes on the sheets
sheet 1
- ¦Caution  Implement D4 on E1
- ¦Caution  Implement D105 on E2
- ¦Caution  Implement R120 and R138 for E3
- ¦Caution  Implement Q1 on E4
sheet 2
- 1608
sheet 3
- 1608
- 1608
- 1005
sheet 4
- DP112 and DP113
- R119 and R121 are placed close to IC100-7pin
- Board Output
- Install a through Hole ofƒ³1.8mm
sheet 6
- Live
- Neutral
- 2012
- 2012
- 2012
- 2012
- One point connection of PFC_DGNDA with C5
